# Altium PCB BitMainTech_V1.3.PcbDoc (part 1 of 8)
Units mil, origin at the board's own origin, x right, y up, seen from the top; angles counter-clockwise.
Board outline 9842.52 x 6082.68 mil, 4 copper layers (Top Layer, Mid-Layer 1, Mid-Layer 2, Bottom Layer); 987 components, 282 nets, 3694 pads, 3174 vias.
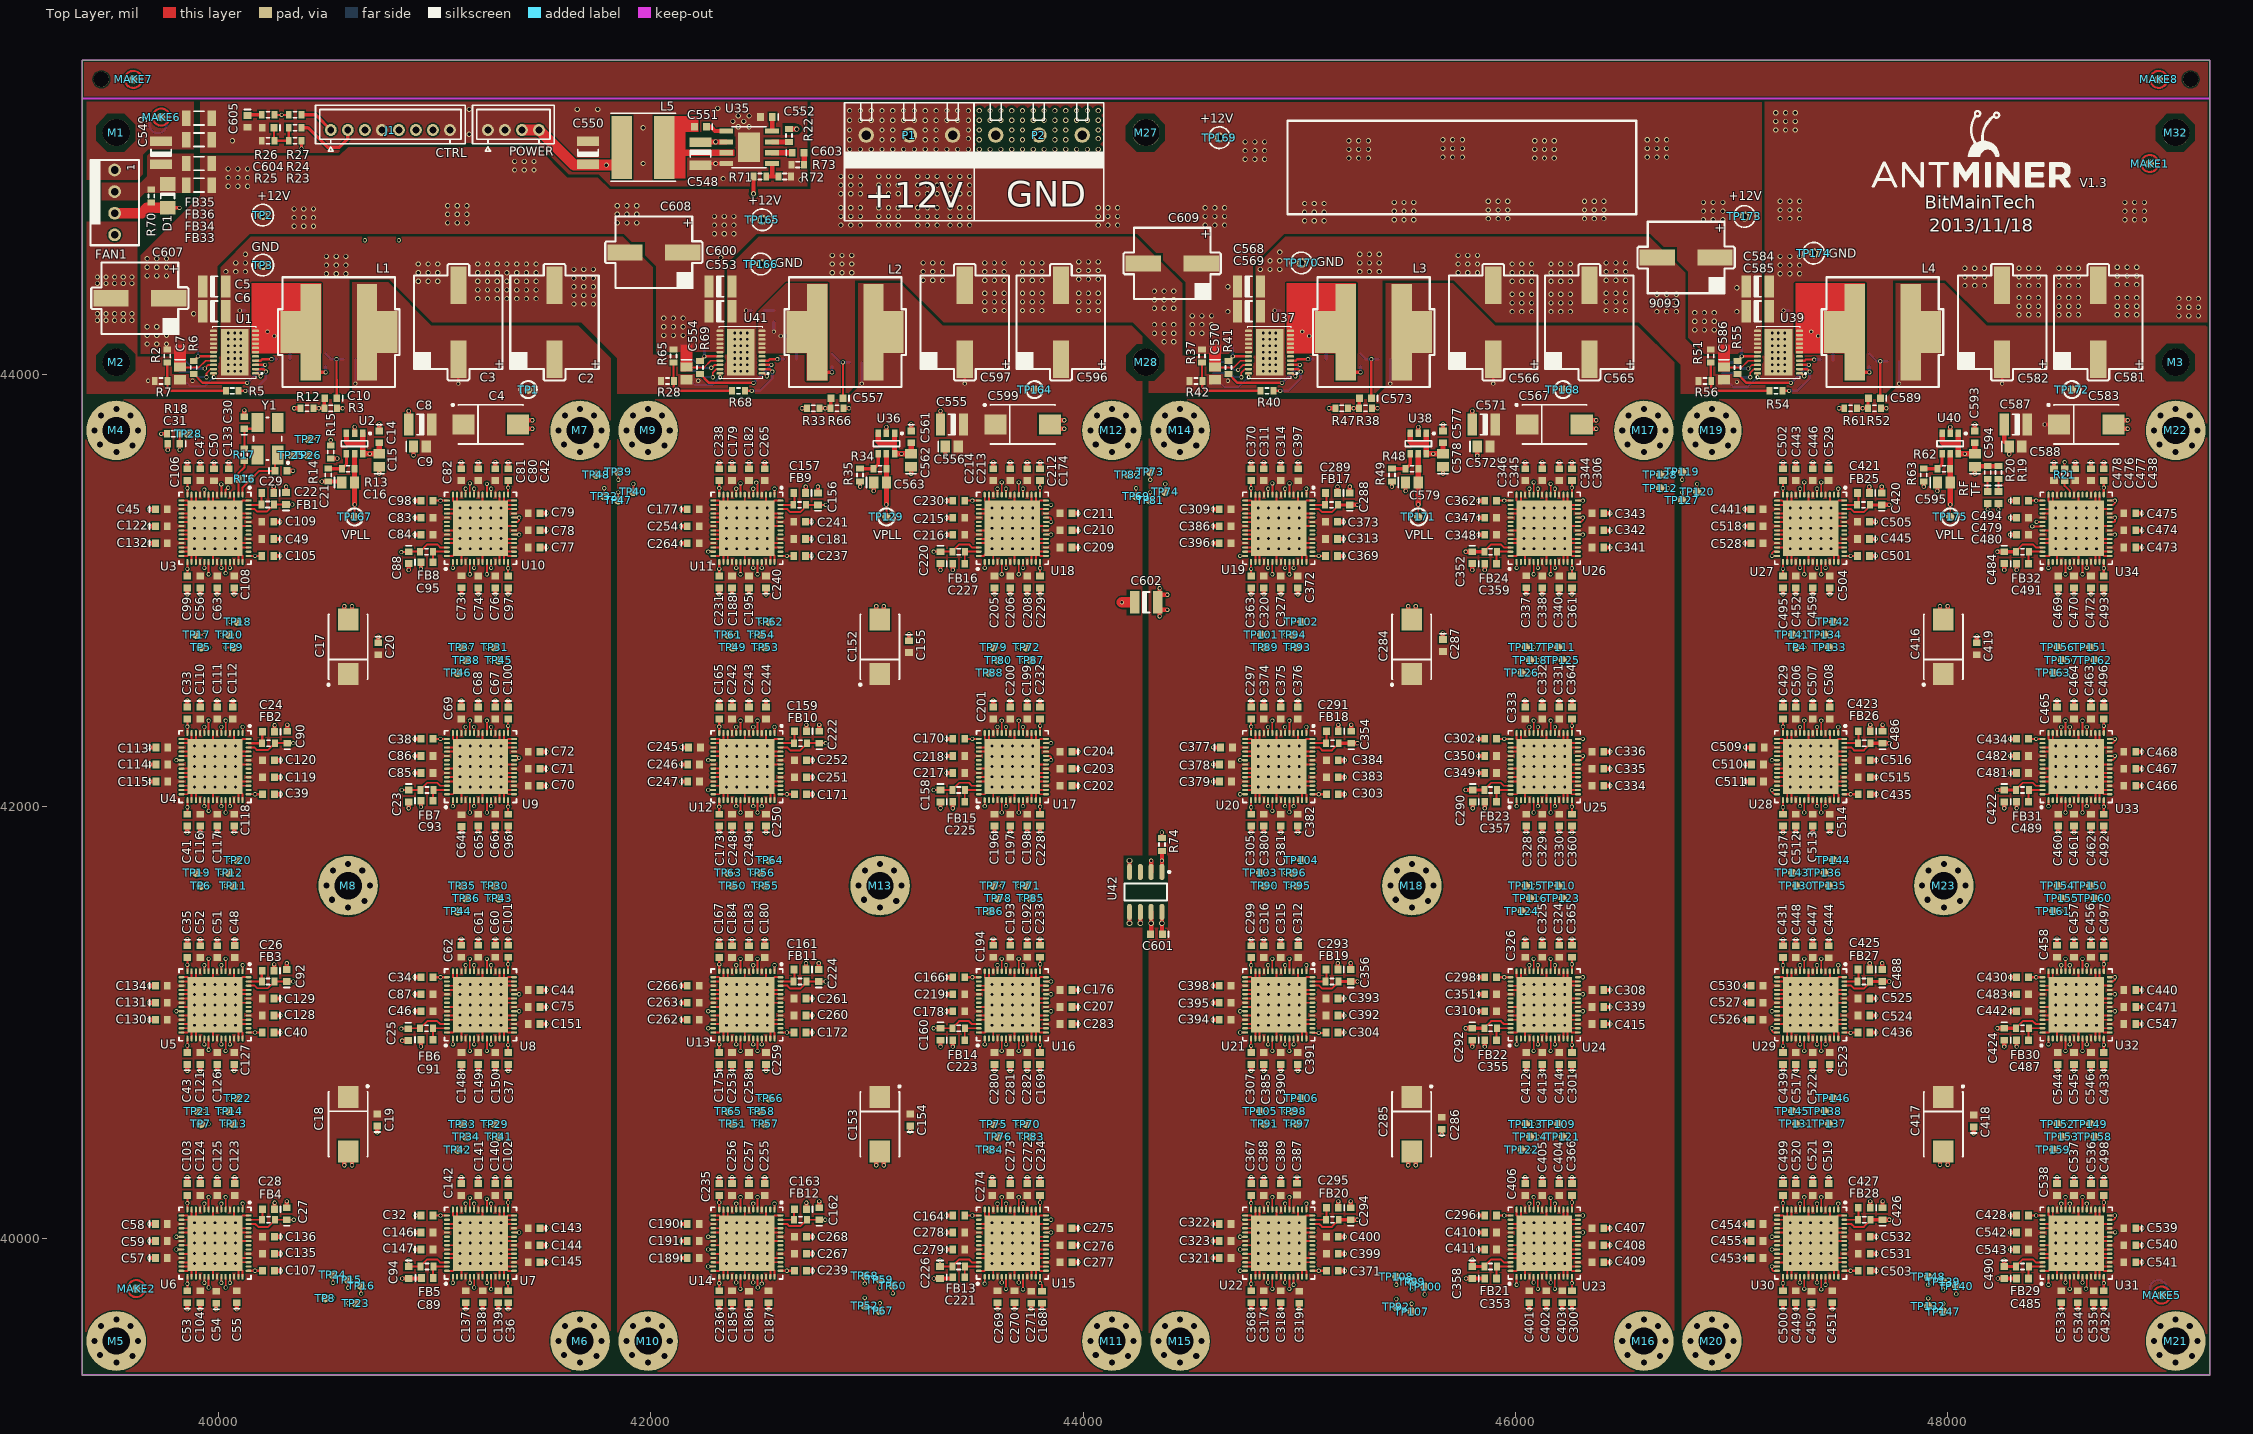
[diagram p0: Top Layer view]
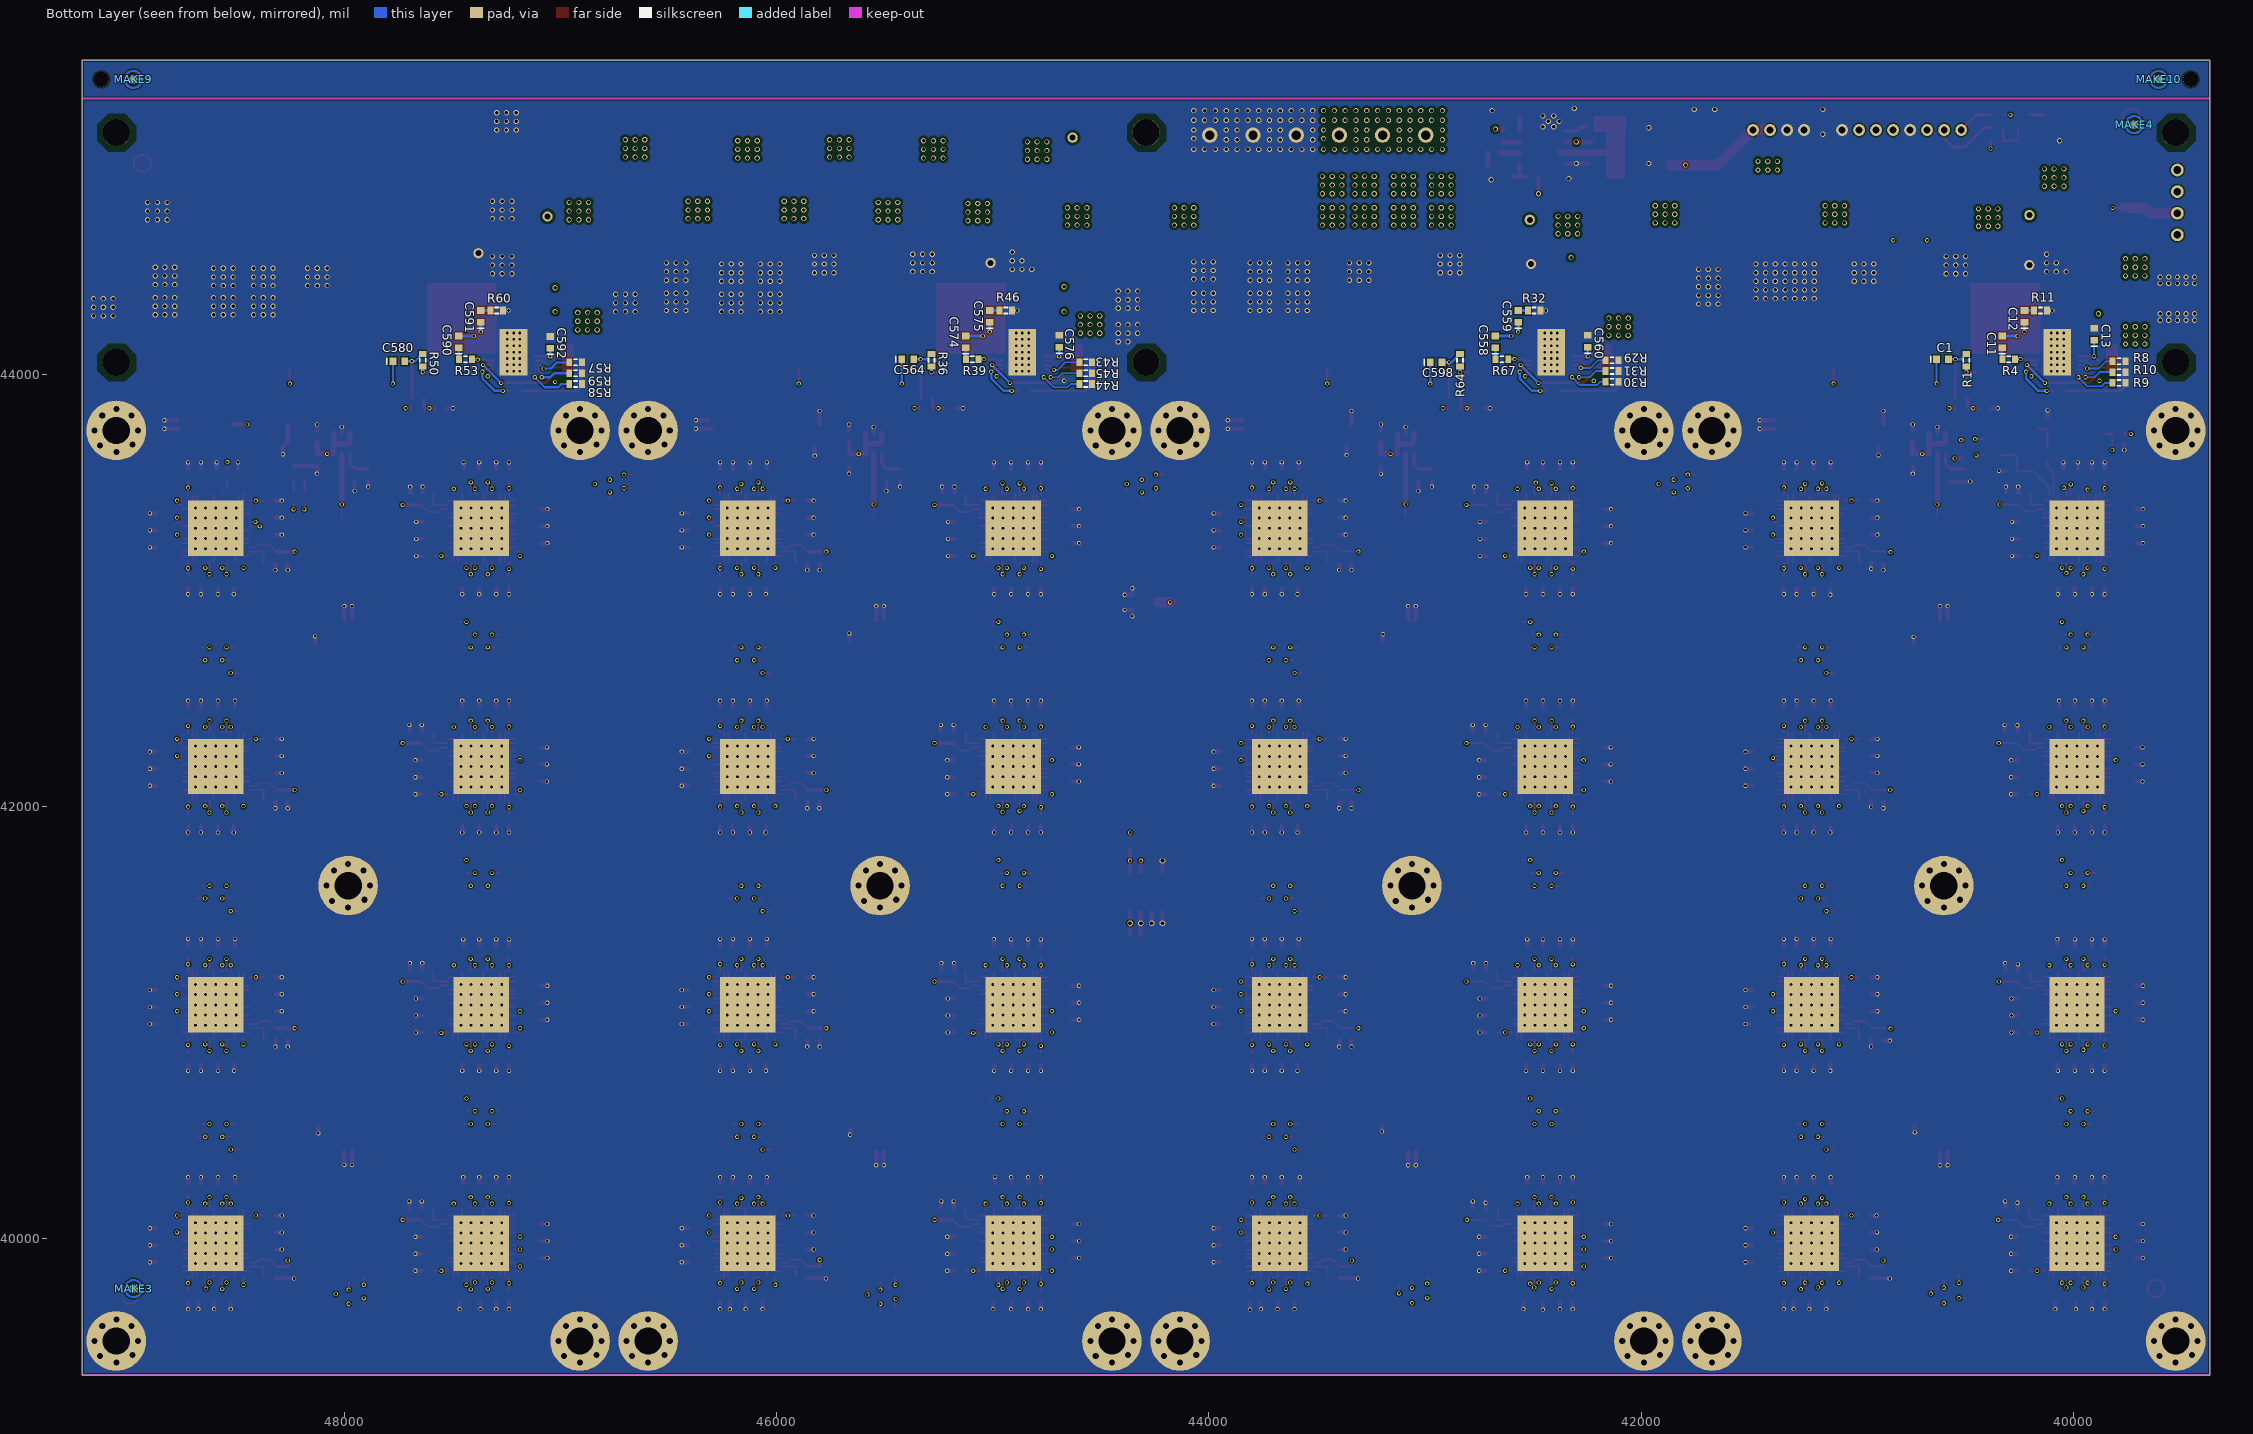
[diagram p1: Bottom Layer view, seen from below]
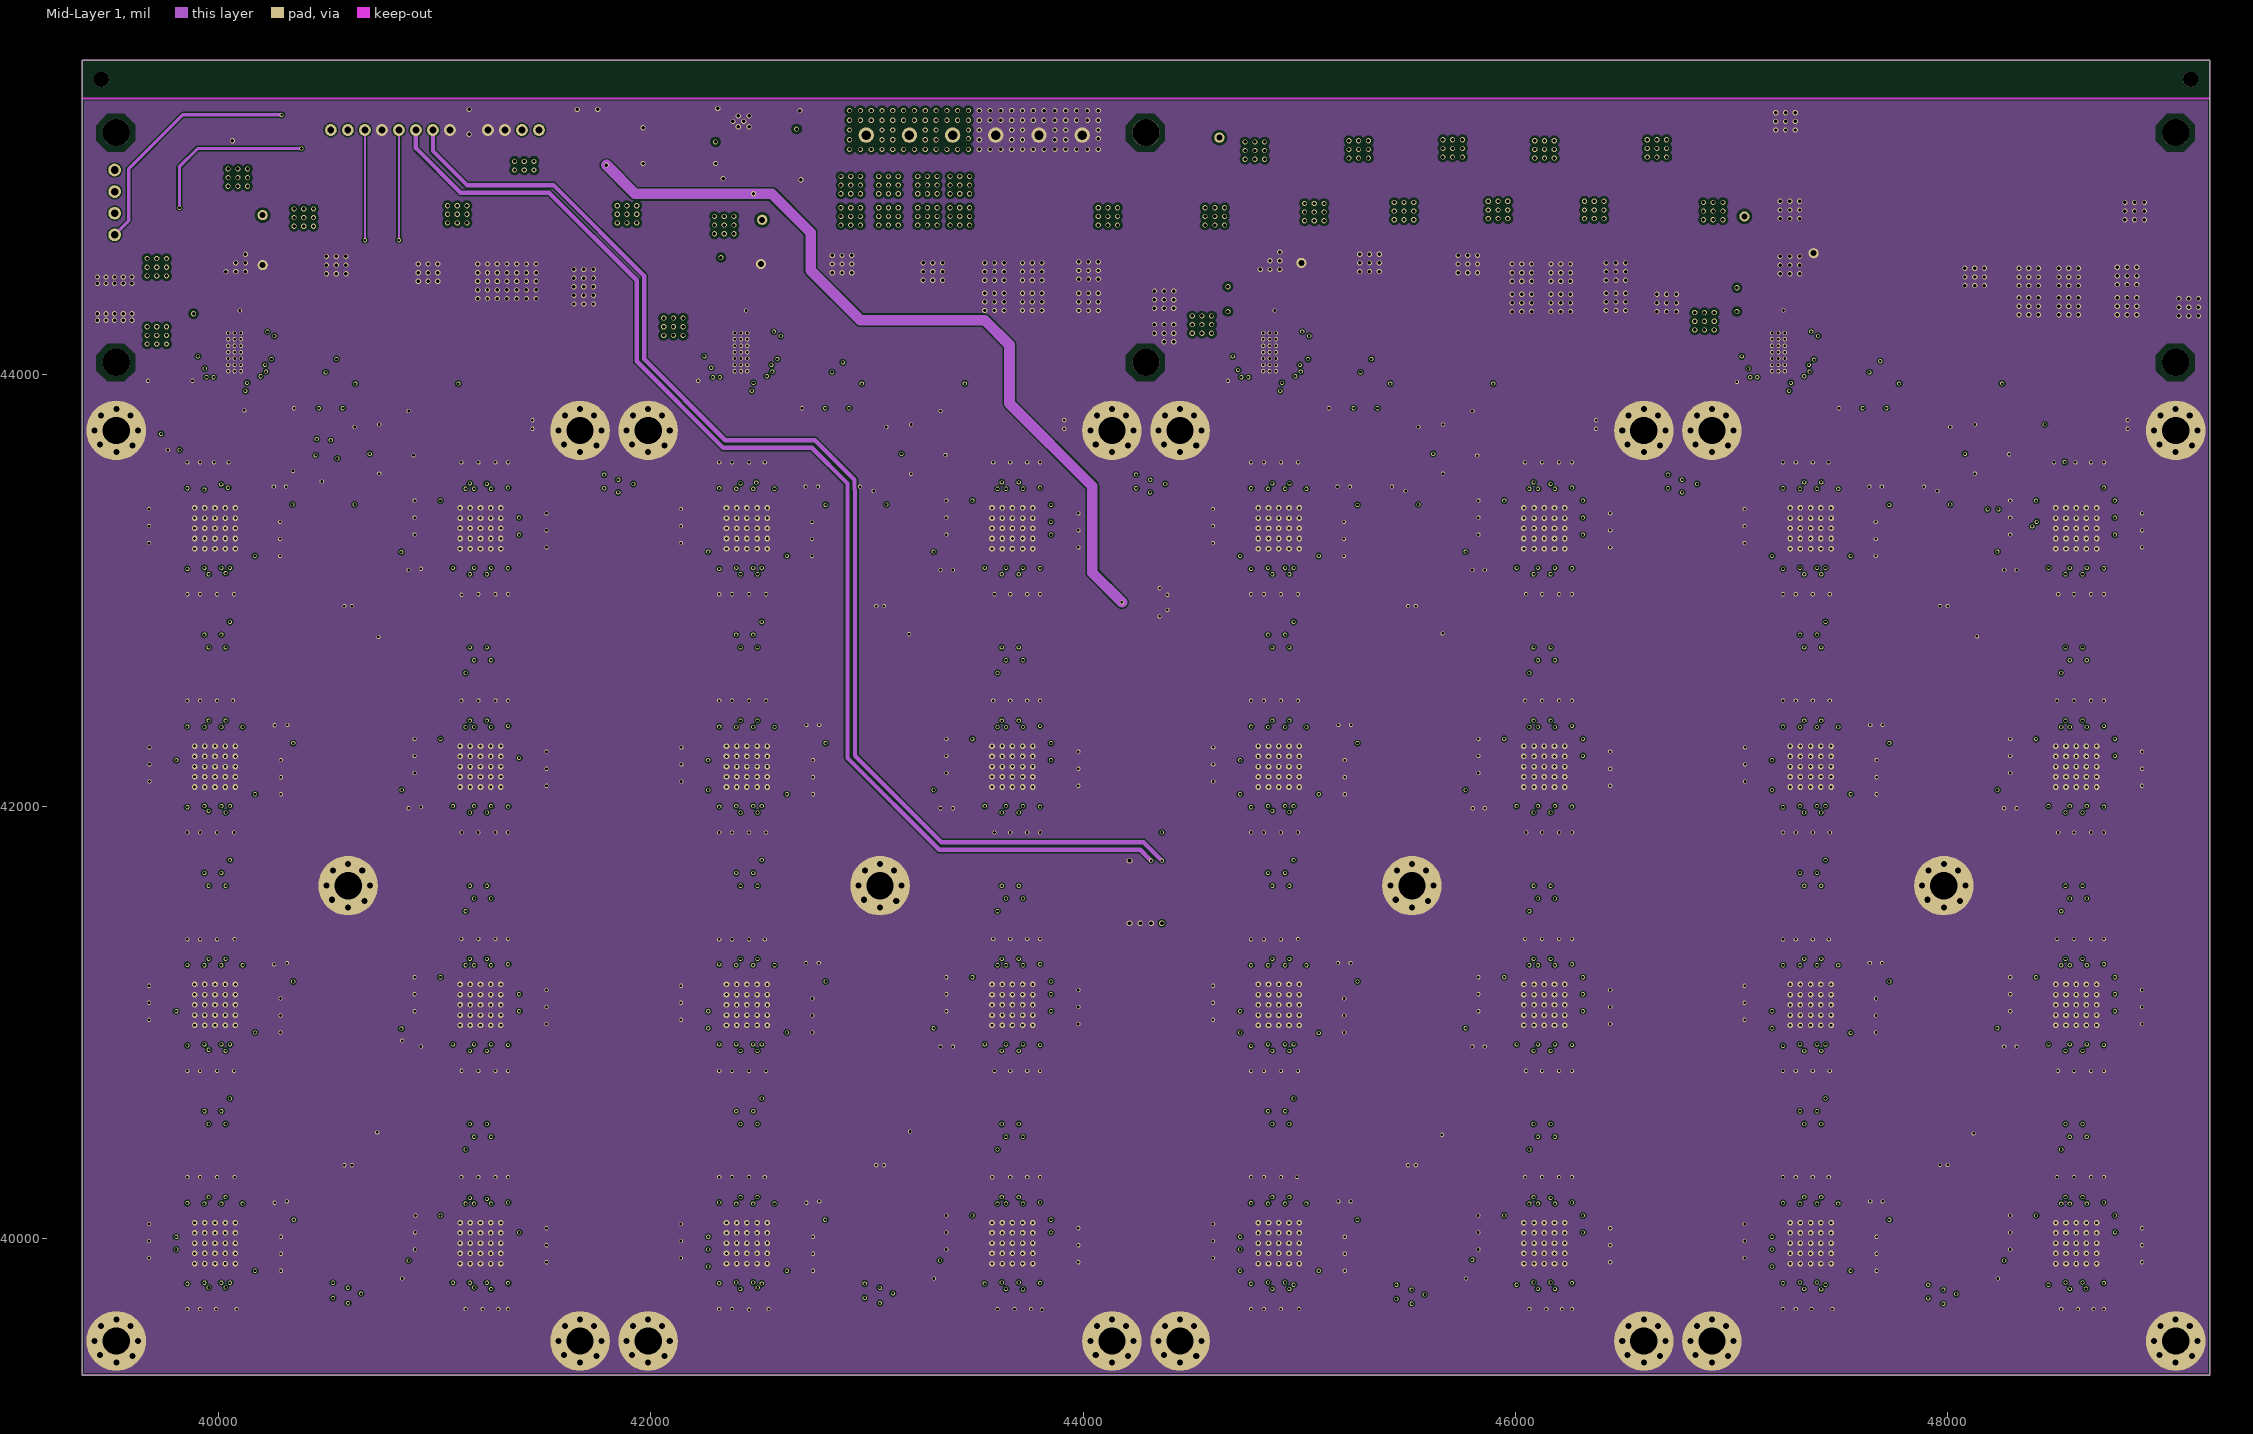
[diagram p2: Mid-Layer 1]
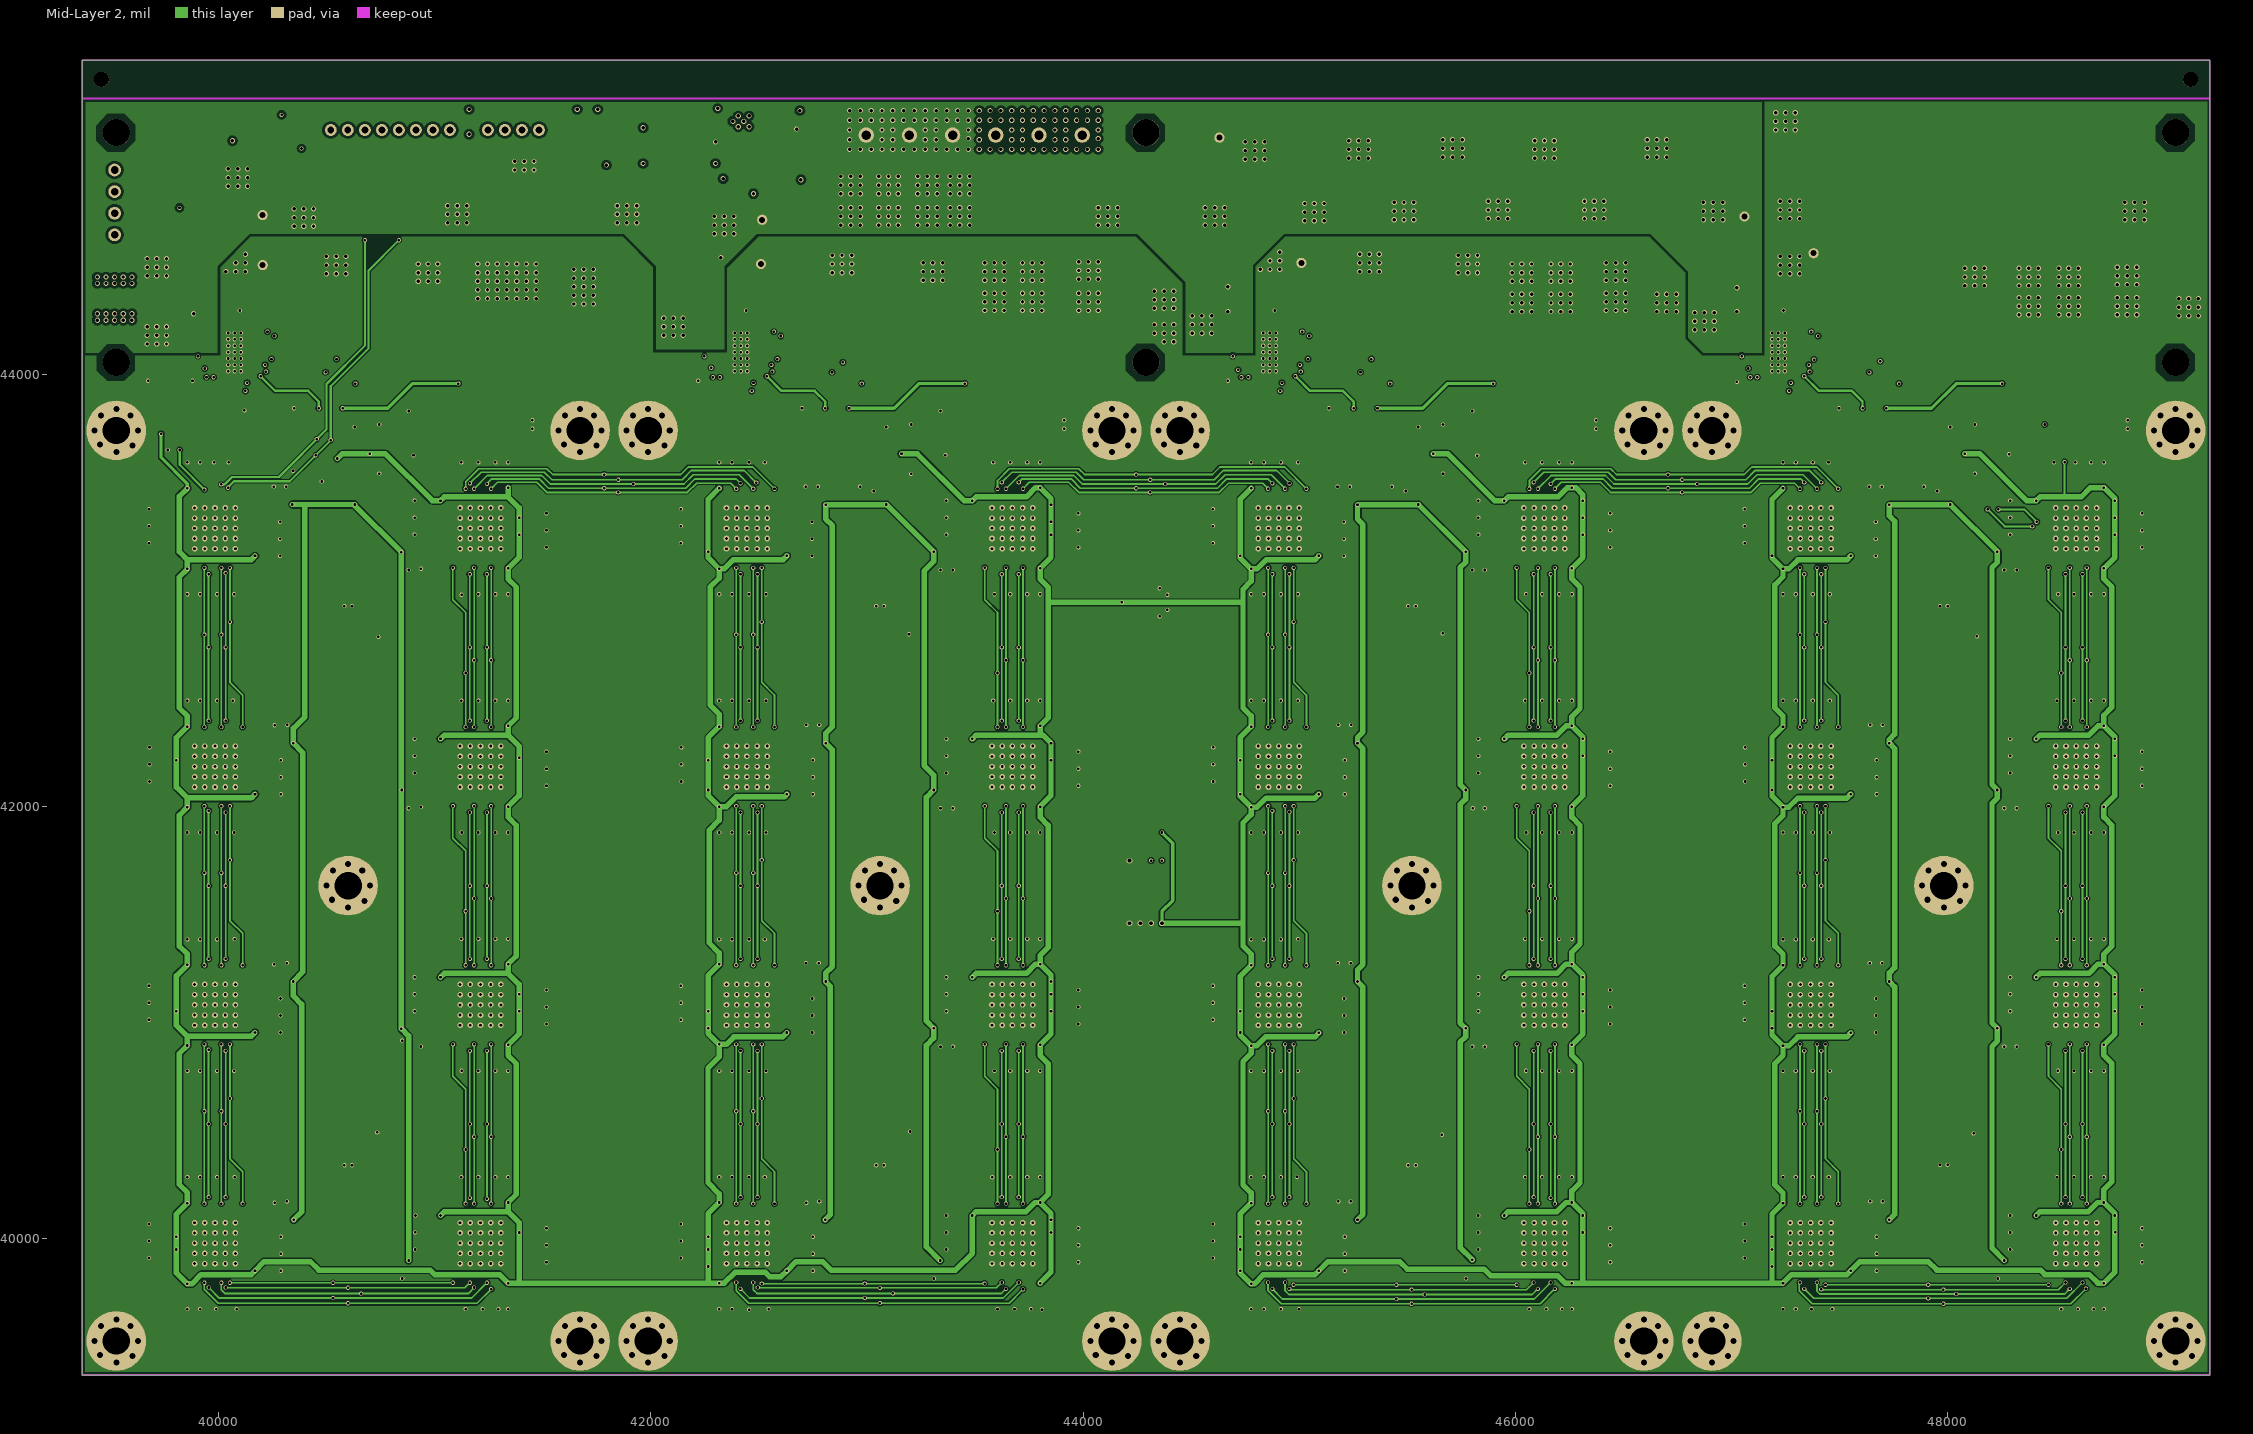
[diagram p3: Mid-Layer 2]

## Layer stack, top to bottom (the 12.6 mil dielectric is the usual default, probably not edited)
Top Layer: signal copper 1.4
Dielectric: core 12.6, FR-4, Dk 4.8
Mid-Layer 1: signal copper 1.4
Dielectric: prepreg 12.6, FR-4, Dk 4.8
Mid-Layer 2: signal copper 1.4
Dielectric: core 12.6, FR-4, Dk 4.8
Bottom Layer: signal copper 1.4

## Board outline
39370.08,45452.76 49212.6,45452.76 49212.6,39370.08 39370.08,39370.08

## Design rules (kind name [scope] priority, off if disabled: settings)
Clearance Clearance_+12V [InNet('+12V')] p1: gap=12
Clearance [All] p2: gap=6
HoleSize [All] p1: absolutevalues=TRUE maxlimit=200 minlimit=11 maxpercent=80.000 minpercent=20.000
MinimumSolderMaskSliver [All] p1: minsoldermaskwidth=0
PolygonConnect [All] p1: connectstyle=Direct reliefconductorwidth=10 reliefentries=4 polygonreliefangle="90 Angle" airgapwidth=10
RoutingVias [All] p1: holewidth=12 width=20 viastyle="Through Hole" minholewidth=12 minwidth=20 maxholewidth=200 maxwidth=200
SilkToSilkClearance [All] p1: silktosilkclearance=2
SilkToSolderMaskClearance SilkscreenOverComponentPads [IsPad] p1: minsilkscreentomaskgap=0 clearancetoexposedcopper=TRUE
SolderMaskExpansion [All] p1: expansion=4
Width Width_+12V [InNet('+12V')] p1: maxlimit=100 minlimit=15 preferedwidth=15
Width Width_VDD [InNet('VDD')] p2: maxlimit=100 minlimit=10 preferedwidth=10
Width Width_GND [InNet('GND')] p3: maxlimit=100 minlimit=8 preferedwidth=15
Width Width_PLL [InNet('VPLL')] p4: maxlimit=50 minlimit=10 preferedwidth=10
Width Width_VCC [InNet('VCC')] p5: maxlimit=50 minlimit=10 preferedwidth=10
Width [All] p6: maxlimit=100 minlimit=8 preferedwidth=8
24 further rules are at their usual default settings.

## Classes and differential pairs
component class HashUnit4: C416 C417 C418 C419 C420 C421 C422 C423 C424 C425 C426 C427 C428 C429 C430 C431 C432 C433 C434 C435 C436 C437 C438 C439 C440 C441 C442 C443 C444 C445 C446 C447 C448 C449 C450 C451 C452 C453 C454 C455 C456 C457 C458 C459 C460 C461 C462 C463 C464 C465 C466 C467 C468 C469 C470 C471 C472 C473 C474 C475 C476 C477 C478 C479 C480 C481 C482 C483 C484 C485 C486 C487 C488 C489 C490 C491 C492 C493 C494 C495 C496 C497 C498 C499 C500 C501 C502 C503 C504 C505 C506 C507 C508 C509 C510 C511 C512 C513 C514 C515 C516 C517 C518 C519 C520 C521 C522 C523 C524 C525 C526 C527 C528 C529 C530 C531 C532 C533 C534 C535 C536 C537 C538 C539 C540 C541 C542 C543 C544 C545 C546 C547 FB25 FB26 FB27 FB28 FB29 FB30 FB31 FB32 M19 M20 M21 M22 M23 R19 R20 R21 RF TF TP4 TP130 TP131 TP132 TP133 TP134 TP135 TP136 TP137 TP138 TP139 TP140 TP141 TP142 TP143 TP144 TP145 TP146 TP147 TP148 TP149 TP150 TP151 TP152 TP153 TP154 TP155 TP156 TP157 TP158 TP159 TP160 TP161 TP162 TP163 U27 U28 U29 U30 U31 U32 U33 U34
component class HashUnit3: C284 C285 C286 C287 C288 C289 C290 C291 C292 C293 C294 C295 C296 C297 C298 C299 C300 C301 C302 C303 C304 C305 C306 C307 C308 C309 C310 C311 C312 C313 C314 C315 C316 C317 C318 C319 C320 C321 C322 C323 C324 C325 C326 C327 C328 C329 C330 C331 C332 C333 C334 C335 C336 C337 C338 C339 C340 C341 C342 C343 C344 C345 C346 C347 C348 C349 C350 C351 C352 C353 C354 C355 C356 C357 C358 C359 C360 C361 C362 C363 C364 C365 C366 C367 C368 C369 C370 C371 C372 C373 C374 C375 C376 C377 C378 C379 C380 C381 C382 C383 C384 C385 C386 C387 C388 C389 C390 C391 C392 C393 C394 C395 C396 C397 C398 C399 C400 C401 C402 C403 C404 C405 C406 C407 C408 C409 C410 C411 C412 C413 C414 C415 FB17 FB18 FB19 FB20 FB21 FB22 FB23 FB24 M14 M15 M16 M17 M18 TP89 TP90 TP91 TP92 TP93 TP94 TP95 TP96 TP97 TP98 TP99 TP100 TP101 TP102 TP103 TP104 TP105 TP106 TP107 TP108 TP109 TP110 TP111 TP112 TP113 TP114 TP115 TP116 TP117 TP118 TP119 TP120 TP121 TP122 TP123 TP124 TP125 TP126 TP127 TP128 U19 U20 U21 U22 U23 U24 U25 U26
component class HashUnit2: C152 C153 C154 C155 C156 C157 C158 C159 C160 C161 C162 C163 C164 C165 C166 C167 C168 C169 C170 C171 C172 C173 C174 C175 C176 C177 C178 C179 C180 C181 C182 C183 C184 C185 C186 C187 C188 C189 C190 C191 C192 C193 C194 C195 C196 C197 C198 C199 C200 C201 C202 C203 C204 C205 C206 C207 C208 C209 C210 C211 C212 C213 C214 C215 C216 C217 C218 C219 C220 C221 C222 C223 C224 C225 C226 C227 C228 C229 C230 C231 C232 C233 C234 C235 C236 C237 C238 C239 C240 C241 C242 C243 C244 C245 C246 C247 C248 C249 C250 C251 C252 C253 C254 C255 C256 C257 C258 C259 C260 C261 C262 C263 C264 C265 C266 C267 C268 C269 C270 C271 C272 C273 C274 C275 C276 C277 C278 C279 C280 C281 C282 C283 FB9 FB10 FB11 FB12 FB13 FB14 FB15 FB16 M9 M10 M11 M12 M13 TP49 TP50 TP51 TP52 TP53 TP54 TP55 TP56 TP57 TP58 TP59 TP60 TP61 TP62 TP63 TP64 TP65 TP66 TP67 TP68 TP69 TP70 TP71 TP72 TP73 TP74 TP75 TP76 TP77 TP78 TP79 TP80 TP81 TP82 TP83 TP84 TP85 TP86 TP87 TP88 U11 U12 U13 U14 U15 U16 U17 U18
component class HashUnit1: C17 C18 C19 C20 C21 C22 C23 C24 C25 C26 C27 C28 C29 C30 C31 C32 C33 C34 C35 C36 C37 C38 C39 C40 C41 C42 C43 C44 C45 C46 C47 C48 C49 C50 C51 C52 C53 C54 C55 C56 C57 C58 C59 C60 C61 C62 C63 C64 C65 C66 C67 C68 C69 C70 C71 C72 C73 C74 C75 C76 C77 C78 C79 C80 C81 C82 C83 C84 C85 C86 C87 C88 C89 C90 C91 C92 C93 C94 C95 C96 C97 C98 C99 C100 C101 C102 C103 C104 C105 C106 C107 C108 C109 C110 C111 C112 C113 C114 C115 C116 C117 C118 C119 C120 C121 C122 C123 C124 C125 C126 C127 C128 C129 C130 C131 C132 C133 C134 C135 C136 C137 C138 C139 C140 C141 C142 C143 C144 C145 C146 C147 C148 C149 C150 C151 FB1 FB2 FB3 FB4 FB5 FB6 FB7 FB8 M4 M5 M6 M7 M8 R15 R16 R17 R18 TP5 TP6 TP7 TP8 TP9 TP10 TP11 TP12 TP13 TP14 TP15 TP16 TP17 TP18 TP19 TP20 TP21 TP22 TP23 TP24 TP25 TP26 TP27 TP28 TP29 TP30 TP31 TP32 TP33 TP34 TP35 TP36 TP37 TP38 TP39 TP40 TP41 TP42 TP43 TP44 TP45 TP46 TP47 TP48 U3 U4 U5 U6 U7 U8 U9 U10 Y1
component class HashPower1: C1 C2 C3 C4 C5 C6 C7 C8 C9 C10 C11 C12 C13 C14 C15 C16 C606 L1 M1 M2 R1 R2 R3 R4 R5 R6 R7 R8 R9 R10 R11 R12 R13 R14 TP1 TP2 TP3 TP167 U1 U2
component class TOP: C548 C549 C550 C551 C552 C601 C602 C603 C604 C605 D1 FAN1 FB33 FB34 FB35 FB36 J1 L5 MAKE1 MAKE2 MAKE3 MAKE4 MAKE5 MAKE6 MAKE7 MAKE8 MAKE9 MAKE10 P1 P2 POWER R22 R23 R24 R25 R26 R27 R70 R71 R72 R73 R74 U35 U42
component class HashPower2: C553 C554 C555 C556 C557 C558 C559 C560 C561 C562 C563 C596 C597 C598 C599 C600 C607 L2 R28 R29 R30 R31 R32 R33 R34 R35 R64 R65 R66 R67 R68 R69 TP129 TP164 TP165 TP166 U36 U41
component class HashPower3: C564 C565 C566 C567 C568 C569 C570 C571 C572 C573 C574 C575 C576 C577 C578 C579 C608 L3 M27 M28 R36 R37 R38 R39 R40 R41 R42 R43 R44 R45 R46 R47 R48 R49 TP168 TP169 TP170 TP171 U37 U38
component class HashPower4: C580 C581 C582 C583 C584 C585 C586 C587 C588 C589 C590 C591 C592 C593 C594 C595 C609 L4 M3 M32 R50 R51 R52 R53 R54 R55 R56 R57 R58 R59 R60 R61 R62 R63 TP172 TP173 TP174 TP175 U39 U40

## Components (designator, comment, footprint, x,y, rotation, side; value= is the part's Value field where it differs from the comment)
C1 "22nF" CC0603(1608) 40606.3,44070 r180 bottom
C2 "1500uF/4V" F12 41555.12,44240.16 r0 top locked
C3 "1500uF/4V" F12 41110.24,44240.16 r0 top locked
C4 "680uF/6.3V" D 41259.84,43767.72 r0 top
C5 "22uF" CC1210(3225) 39980.32,44405.51 r180 top
C6 "22uF" CC1210(3225) 39980.32,44291.34 r180 top
C7 "4.7uF" CC0805(2012) 39822.83,44003.94 r270 top
C8 "47uF" CAPC3225L 40933.07,43767.72 r180 top
C9 "10uF" CAPC2012L 40932,43666 r0 top
C10 "1nF" CC0603(1608) 40519.68,43889.76 r180 top
C11 "100nF" CC0603(1608) 40330,44150 r90 bottom
C12 "2200pF" CC0603(1608) 40227,44268 r90 bottom
C13 "1uF" CC0603(1608) 39905,44185 r90 bottom
C14 "100nF" CC0603(1608) 40744.09,43710.63 r270 top
C15 "10uF" CC0805(2012) 40744.09,43602.36 r90 top
C16 "10uF" CC0805(2012) 40600.39,43500 r0 top
C17 "680uF/6.3V" D 40600,42739.02 r90 top
C18 "680uF/6.3V" D 40600,40530.98 r270 top
C19 "100nF" CC0603(1608) 40735,40550 r90 top
C20 "100nF" CC0603(1608) 40740,42730 r270 top
C21 "100nF" CC0603(1608) 40312.99,43425.2 r90 top
C22 "100nF" CC0603(1608) 40228.35,43450.79 r180 top
C23 "100nF" CC0603(1608) 40879.92,42049.21 r270 top
C24 "100nF" CC0603(1608) 40232.28,42346.46 r180 top
C25 "100nF" CC0603(1608) 40877.95,40944.88 r270 top
C26 "100nF" CC0603(1608) 40230.32,41240.16 r180 top
C27 "100nF" CC0603(1608) 40316.93,40116.14 r90 top
C28 "100nF" CC0603(1608) 40232.28,40137.8 r180 top
C29 "8pF" CC0603(1608) 40289.37,43553.15 r0 top
C30 "8pF" CC0603(1608) 40120.08,43775.59 r90 top
C31 "10uF" CC0603(1608) 39793.31,43679.13 r180 top
C32 "100nF" CC0603(1608) 40964.57,40108.27 r0 top
C33 "100nF" CC0603(1608) 39856.3,42433.07 r270 top
C34 "100nF" CC0603(1608) 40964.57,41210.63 r0 top
C35 "100nF" CC0603(1608) 39856.3,41328.74 r270 top
C36 "100nF" CC0603(1608) 41340.55,39732.28 r90 top
C37 "100nF" CC0603(1608) 41340.55,40834.65 r90 top
C38 "100nF" CC0603(1608) 40964.57,42312.99 r0 top
C39 "100nF" CC0603(1608) 40232.28,42057.09 r180 top
C40 "100nF" CC0603(1608) 40230.32,40954.72 r180 top
C41 "100nF" CC0603(1608) 39856.3,41937.01 r90 top
C42 "100nF" CC0603(1608) 41340.55,43535.43 r270 top
C43 "100nF" CC0603(1608) 39856.3,40834.65 r90 top
C44 "100nF" CC0603(1608) 41460.63,41151.57 r180 top
C45 "100nF" CC0603(1608) 39736.22,43375.98 r0 top
C46 "100nF" CC0603(1608) 40964.57,41053.15 r0 top
C47 "100nF" CC0603(1608) 39915.35,43535.43 r270 top
C48 "100nF" CC0603(1608) 40075,41330 r270 top
C49 "100nF" CC0603(1608) 40228.35,43238.19 r180 top
C50 "100nF" CC0603(1608) 39980,43535 r270 top
C51 "100nF" CC0603(1608) 39994.09,41328.74 r270 top
C52 "100nF" CC0603(1608) 39915.35,41328.74 r270 top
C53 "100nF" CC0603(1608) 39915.35,39732.28 r90 top
C54 "100nF" CC0603(1608) 39990,39730 r90 top
C55 "100nF" CC0603(1608) 40084.65,39732.28 r90 top
C56 "100nF" CC0603(1608) 39915.35,43039.37 r90 top
C57 "100nF" CC0603(1608) 39736.22,39911.42 r0 top
C58 "100nF" CC0603(1608) 39736.22,40068.9 r0 top
C59 "100nF" CC0603(1608) 39736.22,39990.16 r0 top
C60 "100nF" CC0603(1608) 41281.5,41330.71 r270 top
C61 "100nF" CC0603(1608) 41202.76,41330.71 r270 top
C62 "100nF" CC0603(1608) 41124.02,41330.71 r270 top
C63 "100nF" CC0603(1608) 39994.09,43039.37 r90 top
C64 "100nF" CC0603(1608) 41125,41935 r90 top
C65 "100nF" CC0603(1608) 41202.76,41937.01 r90 top
C66 "100nF" CC0603(1608) 41281.5,41937.01 r90 top
C67 "100nF" CC0603(1608) 41281.5,42433.07 r270 top
C68 "100nF" CC0603(1608) 41202.76,42433.07 r270 top
C69 "100nF" CC0603(1608) 41124.02,42433.07 r270 top
C70 "100nF" CC0603(1608) 41460.63,42096.46 r180 top
C71 "100nF" CC0603(1608) 41460.63,42175.2 r180 top
C72 "100nF" CC0603(1608) 41460.63,42253.94 r180 top
C73 "100nF" CC0603(1608) 41125,43040 r90 top
C74 "100nF" CC0603(1608) 41202.76,43039.37 r90 top
C75 "100nF" CC0603(1608) 41460.63,41072.83 r180 top
C76 "100nF" CC0603(1608) 41281.5,43039.37 r90 top
C77 "100nF" CC0603(1608) 41460.63,43198.82 r180 top
C78 "100nF" CC0603(1608) 41460.63,43277.56 r180 top
C79 "100nF" CC0603(1608) 41460.63,43356.3 r180 top
C80 "100nF" CC0603(1608) 41281.5,43535.43 r270 top
C81 "100nF" CC0603(1608) 41202.76,43535.43 r270 top
C82 "100nF" CC0603(1608) 41124.02,43535.43 r270 top
C83 "100nF" CC0603(1608) 40964.57,43336.61 r0 top
C84 "100nF" CC0603(1608) 40964.57,43257.87 r0 top
C85 "100nF" CC0603(1608) 40964.57,42155.51 r0 top
C86 "100nF" CC0603(1608) 40964.57,42234.25 r0 top
C87 "100nF" CC0603(1608) 40964.57,41131.89 r0 top
C88 "100nF" CC0603(1608) 40879.92,43151.57 r270 top
C89 "100nF" CC0603(1608) 40966.54,39818.9 r0 top
C90 "100nF" CC0603(1608) 40318.9,42320.87 r90 top
C91 "100nF" CC0603(1608) 40964.57,40921.26 r0 top
C92 "100nF" CC0603(1608) 40316.93,41218.5 r90 top
C93 "100nF" CC0603(1608) 40964.57,42027.56 r0 top
C94 "100nF" CC0603(1608) 40879.92,39844.49 r270 top
C95 "100nF" CC0603(1608) 40964.57,43129.92 r0 top
C96 "100nF" CC0603(1608) 41340.55,41937.01 r90 top
C97 "100nF" CC0603(1608) 41340.55,43039.37 r90 top
C98 "100nF" CC0603(1608) 40964.57,43415.35 r0 top
C99 "100nF" CC0603(1608) 39856.3,43039.37 r90 top
C100 "100nF" CC0603(1608) 41340.55,42433.07 r270 top
C101 "100nF" CC0603(1608) 41340.55,41330.71 r270 top
C102 "100nF" CC0603(1608) 41340.55,40228.35 r270 top
C103 "100nF" CC0603(1608) 39856.3,40228.35 r270 top
C104 "100nF" CC0603(1608) 39856.3,39732.28 r90 top
C105 "100nF" CC0603(1608) 40228.35,43159.45 r180 top
C106 "100nF" CC0603(1608) 39856.3,43535.43 r270 top
C107 "100nF" CC0603(1608) 40232.28,39852.36 r180 top
C108 "100nF" CC0603(1608) 40072.83,43039.37 r90 top
C109 "100nF" CC0603(1608) 40228.35,43316.93 r180 top
C110 "100nF" CC0603(1608) 39915.35,42433.07 r270 top
C111 "100nF" CC0603(1608) 39994.09,42433.07 r270 top
C112 "100nF" CC0603(1608) 40066.93,42433.07 r270 top
C113 "100nF" CC0603(1608) 39738.19,42273.62 r0 top
C114 "100nF" CC0603(1608) 39738.19,42194.88 r0 top
C115 "100nF" CC0603(1608) 39738.19,42116.14 r0 top
C116 "100nF" CC0603(1608) 39915.35,41937.01 r90 top
C117 "100nF" CC0603(1608) 39994.09,41937.01 r90 top
C118 "100nF" CC0603(1608) 40072.83,41937.01 r90 top
C119 "100nF" CC0603(1608) 40232.28,42135.83 r180 top
C120 "100nF" CC0603(1608) 40232.28,42214.57 r180 top
C121 "100nF" CC0603(1608) 39915.35,40834.65 r90 top
C122 "100nF" CC0603(1608) 39736.22,43297.24 r0 top
C123 "100nF" CC0603(1608) 40075,40228.35 r270 top
C124 "100nF" CC0603(1608) 39915.35,40228.35 r270 top
C125 "100nF" CC0603(1608) 39994.09,40228.35 r270 top
C126 "100nF" CC0603(1608) 39994.09,40834.65 r90 top
C127 "100nF" CC0603(1608) 40072.83,40834.65 r90 top
C128 "100nF" CC0603(1608) 40230.32,41033.46 r180 top
C129 "100nF" CC0603(1608) 40230.32,41112.2 r180 top
C130 "100nF" CC0603(1608) 39736.22,41013.78 r0 top
C131 "100nF" CC0603(1608) 39736.22,41092.52 r0 top
C132 "100nF" CC0603(1608) 39736.22,43218.5 r0 top
C133 "100nF" CC0603(1608) 40047.24,43535.43 r270 top
C134 "100nF" CC0603(1608) 39736.22,41171.26 r0 top
C135 "100nF" CC0603(1608) 40232.28,39931.1 r180 top
C136 "100nF" CC0603(1608) 40232.28,40009.84 r180 top
C137 "100nF" CC0603(1608) 41143.7,39732.28 r90 top
C138 "100nF" CC0603(1608) 41222.44,39732.28 r90 top
C139 "100nF" CC0603(1608) 41295.28,39732.28 r90 top
C140 "100nF" CC0603(1608) 41281.5,40228.35 r270 top
C141 "100nF" CC0603(1608) 41202.76,40228.35 r270 top
C142 "100nF" CC0603(1608) 41124.02,40228.35 r270 top
C143 "100nF" CC0603(1608) 41460.63,40049.21 r180 top
C144 "100nF" CC0603(1608) 41460.63,39970.47 r180 top
C145 "100nF" CC0603(1608) 41460.63,39891.73 r180 top
C146 "100nF" CC0603(1608) 40964.57,40029.53 r0 top
C147 "100nF" CC0603(1608) 40964.57,39950.79 r0 top
C148 "100nF" CC0603(1608) 41125,40835 r90 top
C149 "100nF" CC0603(1608) 41202.76,40834.65 r90 top
C150 "100nF" CC0603(1608) 41281.5,40834.65 r90 top
C151 "100nF" CC0603(1608) 41460.63,40994.09 r180 top
C152 "680uF/6.3V" D 43060,42739.02 r90 top
C153 "680uF/6.3V" D 43060,40530 r270 top
C154 "100nF" CC0603(1608) 43200,40550 r90 top
C155 "100nF" CC0603(1608) 43195,42740 r270 top
C156 "100nF" CC0603(1608) 42773.62,43423.23 r90 top
C157 "100nF" CC0603(1608) 42688.98,43450.79 r180 top
C158 "100nF" CC0603(1608) 43340.55,42049.21 r270 top
C159 "100nF" CC0603(1608) 42692.91,42348.43 r180 top
C160 "100nF" CC0603(1608) 43340.55,40946.85 r270 top
C161 "100nF" CC0603(1608) 42690.94,41246.06 r180 top
C162 "100nF" CC0603(1608) 42779.53,40116.14 r90 top
C163 "100nF" CC0603(1608) 42692.91,40137.8 r180 top
C164 "100nF" CC0603(1608) 43425.2,40108.27 r0 top
C165 "100nF" CC0603(1608) 42316.93,42433.07 r270 top
C166 "100nF" CC0603(1608) 43425.2,41210.63 r0 top
C167 "100nF" CC0603(1608) 42316.93,41328.74 r270 top
C168 "100nF" CC0603(1608) 43810,39730 r90 top
C169 "100nF" CC0603(1608) 43801.18,40834.65 r90 top
C170 "100nF" CC0603(1608) 43425.2,42312.99 r0 top
C171 "100nF" CC0603(1608) 42692.91,42057.09 r180 top
C172 "100nF" CC0603(1608) 42690.94,40954.72 r180 top
C173 "100nF" CC0603(1608) 42316.93,41937.01 r90 top
C174 "100nF" CC0603(1608) 43801.18,43535.43 r270 top
C175 "100nF" CC0603(1608) 42316.93,40834.65 r90 top
C176 "100nF" CC0603(1608) 43921.26,41151.57 r180 top
C177 "100nF" CC0603(1608) 42196.85,43375.98 r0 top
C178 "100nF" CC0603(1608) 43425.2,41053.15 r0 top
C179 "100nF" CC0603(1608) 42375.98,43535.43 r270 top
C180 "100nF" CC0603(1608) 42527.56,41328.74 r270 top
C181 "100nF" CC0603(1608) 42688.98,43238.19 r180 top
C182 "100nF" CC0603(1608) 42454.72,43535.43 r270 top
C183 "100nF" CC0603(1608) 42454.72,41328.74 r270 top
C184 "100nF" CC0603(1608) 42375.98,41328.74 r270 top
C185 "100nF" CC0603(1608) 42375.98,39732.28 r90 top
C186 "100nF" CC0603(1608) 42455,39730 r90 top
C187 "100nF" CC0603(1608) 42545.28,39732.28 r90 top
C188 "100nF" CC0603(1608) 42375.98,43039.37 r90 top
C189 "100nF" CC0603(1608) 42196.85,39911.42 r0 top
C190 "100nF" CC0603(1608) 42196.85,40068.9 r0 top
C191 "100nF" CC0603(1608) 42196.85,39990.16 r0 top
C192 "100nF" CC0603(1608) 43742.13,41330.71 r270 top
C193 "100nF" CC0603(1608) 43663.39,41330.71 r270 top
C194 "100nF" CC0603(1608) 43584.65,41330.71 r270 top
C195 "100nF" CC0603(1608) 42454.72,43039.37 r90 top
C196 "100nF" CC0603(1608) 43590.55,41937.01 r90 top
C197 "100nF" CC0603(1608) 43663.39,41937.01 r90 top
C198 "100nF" CC0603(1608) 43742.13,41937.01 r90 top
C199 "100nF" CC0603(1608) 43742.13,42433.07 r270 top
C200 "100nF" CC0603(1608) 43663.39,42433.07 r270 top
C201 "100nF" CC0603(1608) 43584.65,42433.07 r270 top
C202 "100nF" CC0603(1608) 43921.26,42096.46 r180 top
C203 "100nF" CC0603(1608) 43921.26,42175.2 r180 top
C204 "100nF" CC0603(1608) 43921.26,42253.94 r180 top
C205 "100nF" CC0603(1608) 43590.55,43039.37 r90 top
C206 "100nF" CC0603(1608) 43663.39,43039.37 r90 top
C207 "100nF" CC0603(1608) 43921.26,41072.83 r180 top
C208 "100nF" CC0603(1608) 43742.13,43039.37 r90 top
C209 "100nF" CC0603(1608) 43921.26,43198.82 r180 top
C210 "100nF" CC0603(1608) 43921.26,43277.56 r180 top
C211 "100nF" CC0603(1608) 43921.26,43356.3 r180 top
C212 "100nF" CC0603(1608) 43742.13,43535.43 r270 top
C213 "100nF" CC0603(1608) 43663.39,43535.43 r270 top
C214 "100nF" CC0603(1608) 43584.65,43535.43 r270 top
C215 "100nF" CC0603(1608) 43425.2,43336.61 r0 top
C216 "100nF" CC0603(1608) 43425.2,43257.87 r0 top
C217 "100nF" CC0603(1608) 43425.2,42155.51 r0 top
C218 "100nF" CC0603(1608) 43425.2,42234.25 r0 top
C219 "100nF" CC0603(1608) 43425.2,41131.89 r0 top
C220 "100nF" CC0603(1608) 43340.55,43151.57 r270 top
C221 "100nF" CC0603(1608) 43425.2,39822.83 r0 top
C222 "100nF" CC0603(1608) 42779.53,42320.87 r90 top
C223 "100nF" CC0603(1608) 43425.2,40919.29 r0 top
C224 "100nF" CC0603(1608) 42777.56,41218.5 r90 top
C225 "100nF" CC0603(1608) 43425.2,42021.65 r0 top
C226 "100nF" CC0603(1608) 43338.58,39844.49 r270 top
C227 "100nF" CC0603(1608) 43425.2,43124.02 r0 top
C228 "100nF" CC0603(1608) 43801.18,41937.01 r90 top
C229 "100nF" CC0603(1608) 43801.18,43039.37 r90 top
C230 "100nF" CC0603(1608) 43425.2,43415.35 r0 top
C231 "100nF" CC0603(1608) 42316.93,43039.37 r90 top
C232 "100nF" CC0603(1608) 43801.18,42433.07 r270 top
C233 "100nF" CC0603(1608) 43801.18,41330.71 r270 top
C234 "100nF" CC0603(1608) 43801.18,40228.35 r270 top
C235 "100nF" CC0603(1608) 42316.93,40228.35 r270 top
C236 "100nF" CC0603(1608) 42316.93,39732.28 r90 top
C237 "100nF" CC0603(1608) 42688.98,43159.45 r180 top
C238 "100nF" CC0603(1608) 42316.93,43535.43 r270 top
C239 "100nF" CC0603(1608) 42692.91,39852.36 r180 top
C240 "100nF" CC0603(1608) 42533.46,43039.37 r90 top
C241 "100nF" CC0603(1608) 42688.98,43316.93 r180 top
C242 "100nF" CC0603(1608) 42375.98,42433.07 r270 top
C243 "100nF" CC0603(1608) 42454.72,42433.07 r270 top
C244 "100nF" CC0603(1608) 42533.46,42433.07 r270 top
C245 "100nF" CC0603(1608) 42202.76,42273.62 r0 top
C246 "100nF" CC0603(1608) 42198.82,42194.88 r0 top
C247 "100nF" CC0603(1608) 42198.82,42116.14 r0 top
C248 "100nF" CC0603(1608) 42375.98,41937.01 r90 top
C249 "100nF" CC0603(1608) 42454.72,41937.01 r90 top
C250 "100nF" CC0603(1608) 42533.46,41937.01 r90 top
C251 "100nF" CC0603(1608) 42692.91,42135.83 r180 top
C252 "100nF" CC0603(1608) 42692.91,42214.57 r180 top
C253 "100nF" CC0603(1608) 42375.98,40834.65 r90 top
C254 "100nF" CC0603(1608) 42196.85,43297.24 r0 top
C255 "100nF" CC0603(1608) 42527.56,40228.35 r270 top
C256 "100nF" CC0603(1608) 42375.98,40228.35 r270 top
C257 "100nF" CC0603(1608) 42454.72,40228.35 r270 top
C258 "100nF" CC0603(1608) 42454.72,40834.65 r90 top
C259 "100nF" CC0603(1608) 42533.46,40834.65 r90 top
C260 "100nF" CC0603(1608) 42690.94,41033.46 r180 top
C261 "100nF" CC0603(1608) 42690.94,41112.2 r180 top
C262 "100nF" CC0603(1608) 42196.85,41013.78 r0 top
C263 "100nF" CC0603(1608) 42196.85,41092.52 r0 top
C264 "100nF" CC0603(1608) 42196.85,43218.5 r0 top
C265 "100nF" CC0603(1608) 42527.56,43535.43 r270 top
C266 "100nF" CC0603(1608) 42196.85,41171.26 r0 top
C267 "100nF" CC0603(1608) 42692.91,39931.1 r180 top
C268 "100nF" CC0603(1608) 42692.91,40009.84 r180 top
C269 "100nF" CC0603(1608) 43604.33,39732.28 r90 top
C270 "100nF" CC0603(1608) 43683.07,39732.28 r90 top
C271 "100nF" CC0603(1608) 43760,39730 r90 top
C272 "100nF" CC0603(1608) 43742.13,40228.35 r270 top
C273 "100nF" CC0603(1608) 43663.39,40228.35 r270 top
C274 "100nF" CC0603(1608) 43580,40228.35 r270 top
C275 "100nF" CC0603(1608) 43921.26,40049.21 r180 top
C276 "100nF" CC0603(1608) 43921.26,39970.47 r180 top
C277 "100nF" CC0603(1608) 43921.26,39891.73 r180 top
C278 "100nF" CC0603(1608) 43425.2,40029.53 r0 top
C279 "100nF" CC0603(1608) 43425.2,39950.79 r0 top
C280 "100nF" CC0603(1608) 43590.55,40834.65 r90 top
C281 "100nF" CC0603(1608) 43663.39,40834.65 r90 top
C282 "100nF" CC0603(1608) 43742.13,40834.65 r90 top
C283 "100nF" CC0603(1608) 43921.26,40994.09 r180 top
C284 "680uF/6.3V" D 45520,42739.02 r90 top
C285 "680uF/6.3V" D 45520,40530 r270 top
C286 "100nF" CC0603(1608) 45660,40535 r90 top
C287 "100nF" CC0603(1608) 45665,42745 r270 top
C288 "100nF" CC0603(1608) 45234.23,43423.23 r90 top
C289 "100nF" CC0603(1608) 45149.59,43450.79 r180 top
C290 "100nF" CC0603(1608) 45803.13,42049.21 r270 top
C291 "100nF" CC0603(1608) 45153.53,42348.43 r180 top
C292 "100nF" CC0603(1608) 45801.16,40946.85 r270 top
C293 "100nF" CC0603(1608) 45151.56,41246.06 r180 top
C294 "100nF" CC0603(1608) 45238.17,40116.14 r90 top
C295 "100nF" CC0603(1608) 45153.53,40143.7 r180 top
C296 "100nF" CC0603(1608) 45885.83,40108.27 r0 top
C297 "100nF" CC0603(1608) 44777.56,42433.07 r270 top
C298 "100nF" CC0603(1608) 45885.83,41210.63 r0 top
C299 "100nF" CC0603(1608) 44777.56,41328.74 r270 top
C300 "100nF" CC0603(1608) 46261.81,39732.28 r90 top
C301 "100nF" CC0603(1608) 46261.81,40834.65 r90 top
C302 "100nF" CC0603(1608) 45885.83,42312.99 r0 top
C303 "100nF" CC0603(1608) 45153.54,42057.09 r180 top
C304 "100nF" CC0603(1608) 45151.57,40954.72 r180 top
C305 "100nF" CC0603(1608) 44777.56,41937.01 r90 top
C306 "100nF" CC0603(1608) 46261.81,43535.43 r270 top
C307 "100nF" CC0603(1608) 44777.56,40834.65 r90 top
C308 "100nF" CC0603(1608) 46381.89,41151.57 r180 top
C309 "100nF" CC0603(1608) 44657.48,43375.98 r0 top
C310 "100nF" CC0603(1608) 45885.83,41053.15 r0 top
C311 "100nF" CC0603(1608) 44836.61,43535.43 r270 top
C312 "100nF" CC0603(1608) 44995,41330 r270 top
C313 "100nF" CC0603(1608) 45149.61,43238.19 r180 top
C314 "100nF" CC0603(1608) 44915.35,43535.43 r270 top
C315 "100nF" CC0603(1608) 44915.35,41328.74 r270 top
C316 "100nF" CC0603(1608) 44836.61,41328.74 r270 top
C317 "100nF" CC0603(1608) 44836.61,39732.28 r90 top
C318 "100nF" CC0603(1608) 44915.34,39732.28 r90 top
C319 "100nF" CC0603(1608) 45000,39730 r90 top
C320 "100nF" CC0603(1608) 44836.61,43039.37 r90 top
C321 "100nF" CC0603(1608) 44657.48,39911.42 r0 top
C322 "100nF" CC0603(1608) 44657.48,40068.9 r0 top
C323 "100nF" CC0603(1608) 44657.48,39990.16 r0 top
C324 "100nF" CC0603(1608) 46202.76,41330.71 r270 top
C325 "100nF" CC0603(1608) 46124.02,41330.71 r270 top
C326 "100nF" CC0603(1608) 46045.28,41330.71 r270 top
C327 "100nF" CC0603(1608) 44915.35,43039.37 r90 top
C328 "100nF" CC0603(1608) 46051.16,41937.01 r90 top
C329 "100nF" CC0603(1608) 46124.02,41937.01 r90 top
C330 "100nF" CC0603(1608) 46202.76,41937.01 r90 top
C331 "100nF" CC0603(1608) 46202.76,42433.07 r270 top
C332 "100nF" CC0603(1608) 46124.02,42433.07 r270 top
C333 "100nF" CC0603(1608) 46045.28,42433.07 r270 top
C334 "100nF" CC0603(1608) 46381.89,42096.46 r180 top
C335 "100nF" CC0603(1608) 46381.89,42175.2 r180 top
C336 "100nF" CC0603(1608) 46381.89,42253.94 r180 top
C337 "100nF" CC0603(1608) 46050,43040 r90 top
C338 "100nF" CC0603(1608) 46124.02,43039.37 r90 top
C339 "100nF" CC0603(1608) 46381.89,41072.83 r180 top
C340 "100nF" CC0603(1608) 46202.76,43039.37 r90 top
C341 "100nF" CC0603(1608) 46381.89,43198.82 r180 top
C342 "100nF" CC0603(1608) 46381.89,43277.56 r180 top
C343 "100nF" CC0603(1608) 46381.89,43356.3 r180 top
C344 "100nF" CC0603(1608) 46202.76,43535.43 r270 top
C345 "100nF" CC0603(1608) 46124.02,43535.43 r270 top
C346 "100nF" CC0603(1608) 46045.28,43535.43 r270 top
C347 "100nF" CC0603(1608) 45885.83,43336.61 r0 top
C348 "100nF" CC0603(1608) 45885.83,43257.87 r0 top
C349 "100nF" CC0603(1608) 45885.83,42155.51 r0 top
C350 "100nF" CC0603(1608) 45885.83,42234.25 r0 top
C351 "100nF" CC0603(1608) 45885.83,41131.89 r0 top
C352 "100nF" CC0603(1608) 45801.16,43151.57 r270 top
C353 "100nF" CC0603(1608) 45885.81,39816.93 r0 top
C354 "100nF" CC0603(1608) 45240.14,42320.87 r90 top
C355 "100nF" CC0603(1608) 45885.81,40919.29 r0 top
C356 "100nF" CC0603(1608) 45238.17,41218.5 r90 top
C357 "100nF" CC0603(1608) 45885.81,42021.65 r0 top
C358 "100nF" CC0603(1608) 45801.16,39844.49 r270 top
C359 "100nF" CC0603(1608) 45885.81,43124.02 r0 top
C360 "100nF" CC0603(1608) 46261.81,41937.01 r90 top
C361 "100nF" CC0603(1608) 46261.81,43039.37 r90 top
C362 "100nF" CC0603(1608) 45885.83,43415.35 r0 top
C363 "100nF" CC0603(1608) 44777.56,43039.37 r90 top
C364 "100nF" CC0603(1608) 46261.81,42433.07 r270 top
C365 "100nF" CC0603(1608) 46261.81,41330.71 r270 top
C366 "100nF" CC0603(1608) 46261.81,40228.35 r270 top
C367 "100nF" CC0603(1608) 44777.56,40228.35 r270 top
C368 "100nF" CC0603(1608) 44777.56,39732.28 r90 top
C369 "100nF" CC0603(1608) 45149.61,43159.45 r180 top
C370 "100nF" CC0603(1608) 44777.56,43535.43 r270 top
C371 "100nF" CC0603(1608) 45153.54,39852.36 r180 top
C372 "100nF" CC0603(1608) 44994.09,43039.37 r90 top
C373 "100nF" CC0603(1608) 45149.61,43316.93 r180 top
C374 "100nF" CC0603(1608) 44836.61,42433.07 r270 top
C375 "100nF" CC0603(1608) 44915.35,42433.07 r270 top
C376 "100nF" CC0603(1608) 44994.09,42433.07 r270 top
C377 "100nF" CC0603(1608) 44663.39,42273.62 r0 top
C378 "100nF" CC0603(1608) 44659.45,42194.88 r0 top
C379 "100nF" CC0603(1608) 44659.45,42116.14 r0 top
C380 "100nF" CC0603(1608) 44836.61,41937.01 r90 top
C381 "100nF" CC0603(1608) 44915.35,41937.01 r90 top
C382 "100nF" CC0603(1608) 44994.09,41937.01 r90 top
C383 "100nF" CC0603(1608) 45153.54,42135.83 r180 top
C384 "100nF" CC0603(1608) 45153.54,42214.57 r180 top
C385 "100nF" CC0603(1608) 44836.61,40834.65 r90 top
C386 "100nF" CC0603(1608) 44657.48,43297.24 r0 top
C387 "100nF" CC0603(1608) 44990,40230 r270 top
C388 "100nF" CC0603(1608) 44836.61,40228.35 r270 top
C389 "100nF" CC0603(1608) 44915.35,40228.35 r270 top
C390 "100nF" CC0603(1608) 44915.35,40834.65 r90 top
C391 "100nF" CC0603(1608) 44994.09,40834.65 r90 top
C392 "100nF" CC0603(1608) 45151.57,41033.46 r180 top
C393 "100nF" CC0603(1608) 45151.57,41112.2 r180 top
C394 "100nF" CC0603(1608) 44657.48,41013.78 r0 top
C395 "100nF" CC0603(1608) 44657.48,41092.52 r0 top
C396 "100nF" CC0603(1608) 44657.48,43218.5 r0 top
C397 "100nF" CC0603(1608) 44995,43535 r270 top
C398 "100nF" CC0603(1608) 44657.48,41171.26 r0 top
C399 "100nF" CC0603(1608) 45153.54,39931.1 r180 top
C400 "100nF" CC0603(1608) 45153.54,40009.84 r180 top
C401 "100nF" CC0603(1608) 46064.96,39732.28 r90 top
C402 "100nF" CC0603(1608) 46143.7,39732.28 r90 top
C403 "100nF" CC0603(1608) 46216.52,39732.28 r90 top
C404 "100nF" CC0603(1608) 46202.76,40228.35 r270 top
C405 "100nF" CC0603(1608) 46124.02,40228.35 r270 top
C406 "100nF" CC0603(1608) 46045.28,40228.35 r270 top
C407 "100nF" CC0603(1608) 46381.89,40049.21 r180 top
C408 "100nF" CC0603(1608) 46381.89,39970.47 r180 top
C409 "100nF" CC0603(1608) 46381.89,39891.73 r180 top
C410 "100nF" CC0603(1608) 45885.83,40029.53 r0 top
C411 "100nF" CC0603(1608) 45885.83,39950.79 r0 top
C412 "100nF" CC0603(1608) 46050,40835 r90 top
C413 "100nF" CC0603(1608) 46124.02,40834.65 r90 top
C414 "100nF" CC0603(1608) 46202.76,40834.65 r90 top
C415 "100nF" CC0603(1608) 46381.89,40994.09 r180 top
C416 "680uF/6.3V" D 47980,42739.02 r90 top
C417 "680uF/6.3V" D 47980,40530 r270 top
C418 "100nF" CC0603(1608) 48120,40545 r90 top
C419 "100nF" CC0603(1608) 48135,42730 r270 top
C420 "100nF" CC0603(1608) 47694.88,43423.23 r90 top
C421 "100nF" CC0603(1608) 47610.24,43450.79 r180 top
C422 "100nF" CC0603(1608) 48261.81,42049.21 r270 top
C423 "100nF" CC0603(1608) 47614.17,42348.43 r180 top
C424 "100nF" CC0603(1608) 48261.81,40946.85 r270 top
C425 "100nF" CC0603(1608) 47612.2,41246.06 r180 top
C426 "100nF" CC0603(1608) 47698.82,40116.14 r90 top
C427 "100nF" CC0603(1608) 47614.17,40143.7 r180 top
C428 "100nF" CC0603(1608) 48346.46,40108.27 r0 top
C429 "100nF" CC0603(1608) 47238.19,42433.07 r270 top
C430 "100nF" CC0603(1608) 48346.46,41210.63 r0 top
C431 "100nF" CC0603(1608) 47238.19,41328.74 r270 top
C432 "100nF" CC0603(1608) 48722.44,39732.28 r90 top
C433 "100nF" CC0603(1608) 48722.44,40834.65 r90 top
C434 "100nF" CC0603(1608) 48346.46,42312.99 r0 top
C435 "100nF" CC0603(1608) 47614.17,42057.09 r180 top
C436 "100nF" CC0603(1608) 47612.2,40954.72 r180 top
C437 "100nF" CC0603(1608) 47238.19,41937.01 r90 top
C438 "100nF" CC0603(1608) 48722.44,43535.43 r270 top
C439 "100nF" CC0603(1608) 47238.19,40834.65 r90 top
C440 "100nF" CC0603(1608) 48842.52,41151.57 r180 top
C441 "100nF" CC0603(1608) 47118.11,43375.98 r0 top
C442 "100nF" CC0603(1608) 48346.46,41053.15 r0 top
C443 "100nF" CC0603(1608) 47297.24,43535.43 r270 top
C444 "100nF" CC0603(1608) 47450,41328.35 r270 top
C445 "100nF" CC0603(1608) 47610.24,43238.19 r180 top
C446 "100nF" CC0603(1608) 47375.98,43535.43 r270 top
C447 "100nF" CC0603(1608) 47375.98,41328.74 r270 top
C448 "100nF" CC0603(1608) 47297.24,41328.74 r270 top
C449 "100nF" CC0603(1608) 47297.24,39732.28 r90 top
C450 "100nF" CC0603(1608) 47370,39730 r90 top
C451 "100nF" CC0603(1608) 47466.54,39732.28 r90 top
C452 "100nF" CC0603(1608) 47297.24,43039.37 r90 top
C453 "100nF" CC0603(1608) 47118.11,39911.42 r0 top
C454 "100nF" CC0603(1608) 47118.11,40068.9 r0 top
C455 "100nF" CC0603(1608) 47118.11,39990.16 r0 top
C456 "100nF" CC0603(1608) 48663.39,41330.71 r270 top
C457 "100nF" CC0603(1608) 48584.65,41330.71 r270 top
C458 "100nF" CC0603(1608) 48505.91,41330.71 r270 top
C459 "100nF" CC0603(1608) 47375.98,43039.37 r90 top
C460 "100nF" CC0603(1608) 48511.81,41937.01 r90 top
C461 "100nF" CC0603(1608) 48584.65,41937.01 r90 top
C462 "100nF" CC0603(1608) 48663.39,41937.01 r90 top
C463 "100nF" CC0603(1608) 48663.39,42433.07 r270 top
C464 "100nF" CC0603(1608) 48584.65,42433.07 r270 top
C465 "100nF" CC0603(1608) 48505.91,42433.07 r270 top
C466 "100nF" CC0603(1608) 48842.52,42096.46 r180 top
C467 "100nF" CC0603(1608) 48842.52,42175.2 r180 top
C468 "100nF" CC0603(1608) 48842.52,42253.94 r180 top
C469 "100nF" CC0603(1608) 48511.81,43039.37 r90 top
C470 "100nF" CC0603(1608) 48584.65,43039.37 r90 top
C471 "100nF" CC0603(1608) 48842.52,41072.83 r180 top
C472 "100nF" CC0603(1608) 48663.39,43039.37 r90 top
C473 "100nF" CC0603(1608) 48842.52,43198.82 r180 top
C474 "100nF" CC0603(1608) 48842.52,43277.56 r180 top
C475 "100nF" CC0603(1608) 48842.52,43356.3 r180 top
C476 "100nF" CC0603(1608) 48663.39,43535.43 r270 top
C477 "100nF" CC0603(1608) 48590.55,43535.43 r270 top
C478 "100nF" CC0603(1608) 48492.13,43535.43 r270 top
C479 "100nF" CC0603(1608) 48346.46,43336.61 r0 top
C480 "100nF" CC0603(1608) 48346.46,43257.87 r0 top
C481 "100nF" CC0603(1608) 48346.46,42155.51 r0 top
C482 "100nF" CC0603(1608) 48346.46,42234.25 r0 top
C483 "100nF" CC0603(1608) 48346.46,41131.89 r0 top
C484 "100nF" CC0603(1608) 48261.81,43151.57 r270 top
C485 "100nF" CC0603(1608) 48346.46,39816.93 r0 top
C486 "100nF" CC0603(1608) 47698.82,42320.87 r90 top
C487 "100nF" CC0603(1608) 48346.46,40919.29 r0 top
C488 "100nF" CC0603(1608) 47696.85,41218.5 r90 top
C489 "100nF" CC0603(1608) 48346.46,42021.65 r0 top
C490 "100nF" CC0603(1608) 48261.81,39844.49 r270 top
C491 "100nF" CC0603(1608) 48346.46,43124.02 r0 top
C492 "100nF" CC0603(1608) 48722.44,41937.01 r90 top
C493 "100nF" CC0603(1608) 48722.44,43039.37 r90 top
C494 "100nF" CC0603(1608) 48346.46,43415.35 r0 top
C495 "100nF" CC0603(1608) 47238.19,43039.37 r90 top
C496 "100nF" CC0603(1608) 48722.44,42433.07 r270 top
C497 "100nF" CC0603(1608) 48722.44,41330.71 r270 top
C498 "100nF" CC0603(1608) 48722.44,40228.35 r270 top
C499 "100nF" CC0603(1608) 47238.19,40228.35 r270 top
C500 "100nF" CC0603(1608) 47238.19,39732.28 r90 top
C501 "100nF" CC0603(1608) 47610.24,43159.45 r180 top
C502 "100nF" CC0603(1608) 47238.19,43535.43 r270 top
C503 "100nF" CC0603(1608) 47614.17,39852.36 r180 top
C504 "100nF" CC0603(1608) 47454.72,43039.37 r90 top
C505 "100nF" CC0603(1608) 47610.24,43316.93 r180 top
C506 "100nF" CC0603(1608) 47297.24,42433.07 r270 top
C507 "100nF" CC0603(1608) 47375.98,42433.07 r270 top
C508 "100nF" CC0603(1608) 47454.72,42433.07 r270 top
C509 "100nF" CC0603(1608) 47124.02,42273.62 r0 top
C510 "100nF" CC0603(1608) 47120.08,42194.88 r0 top
C511 "100nF" CC0603(1608) 47120.08,42116.14 r0 top
C512 "100nF" CC0603(1608) 47297.24,41937.01 r90 top
C513 "100nF" CC0603(1608) 47375.98,41937.01 r90 top
C514 "100nF" CC0603(1608) 47454.72,41937.01 r90 top
C515 "100nF" CC0603(1608) 47614.17,42135.83 r180 top
C516 "100nF" CC0603(1608) 47614.17,42214.57 r180 top
C517 "100nF" CC0603(1608) 47297.24,40834.65 r90 top
C518 "100nF" CC0603(1608) 47118.11,43297.24 r0 top
C519 "100nF" CC0603(1608) 47450,40228.35 r270 top
C520 "100nF" CC0603(1608) 47297.24,40228.35 r270 top
C521 "100nF" CC0603(1608) 47375.98,40228.35 r270 top
C522 "100nF" CC0603(1608) 47375.98,40834.65 r90 top
C523 "100nF" CC0603(1608) 47454.72,40834.65 r90 top
C524 "100nF" CC0603(1608) 47612.2,41033.46 r180 top
C525 "100nF" CC0603(1608) 47612.2,41112.2 r180 top
C526 "100nF" CC0603(1608) 47118.11,41013.78 r0 top
C527 "100nF" CC0603(1608) 47118.11,41092.52 r0 top
C528 "100nF" CC0603(1608) 47118.11,43218.5 r0 top
C529 "100nF" CC0603(1608) 47448.82,43535.43 r270 top
C530 "100nF" CC0603(1608) 47118.11,41171.26 r0 top
C531 "100nF" CC0603(1608) 47614.17,39931.1 r180 top
C532 "100nF" CC0603(1608) 47614.17,40009.84 r180 top
C533 "100nF" CC0603(1608) 48525.59,39732.28 r90 top
C534 "100nF" CC0603(1608) 48602.36,39732.28 r90 top
C535 "100nF" CC0603(1608) 48675.2,39732.28 r90 top
C536 "100nF" CC0603(1608) 48663.39,40228.35 r270 top
C537 "100nF" CC0603(1608) 48584.65,40228.35 r270 top
C538 "100nF" CC0603(1608) 48505.91,40228.35 r270 top
C539 "100nF" CC0603(1608) 48842.52,40049.21 r180 top
C540 "100nF" CC0603(1608) 48842.52,39970.47 r180 top
C541 "100nF" CC0603(1608) 48842.52,39891.73 r180 top
C542 "100nF" CC0603(1608) 48346.46,40029.53 r0 top
C543 "100nF" CC0603(1608) 48346.46,39950.79 r0 top
C544 "100nF" CC0603(1608) 48510,40835 r90 top
C545 "100nF" CC0603(1608) 48584.65,40834.65 r90 top
C546 "100nF" CC0603(1608) 48663.39,40834.65 r90 top
C547 "100nF" CC0603(1608) 48842.52,40994.09 r180 top
C548 "4.7uF" CAP1210(3225)_TAN 42230,45020 r90 top
C549 "22uF" CAP1210(3225)_TAN 39735,45025 r270 top
C550 "22uF" CAP1210(3225)_TAN 41710,45025 r270 top
C551 "10nF" CC0603(1608) 42230,45145 r180 top
C552 "100nF" CC0603(1608) 42535,45190 r180 top
C553 "22uF" CC1210(3225) 42322.83,44291.34 r180 top
C554 "4.7uF" CC0805(2012) 42165.35,44003.94 r270 top
C555 "47uF" CAPC3225L 43393.7,43767.72 r180 top
C556 "10uF" CAPC2012L 43392.63,43666 r0 top
C557 "1nF" CC0603(1608) 42862.2,43889.76 r180 top
C558 "100nF" CC0603(1608) 42675,44150 r90 bottom
C559 "2200pF" CC0603(1608) 42569.52,44268 r90 bottom
C560 "1uF" CC0603(1608) 42248.03,44152.56 r90 bottom
C561 "100nF" CC0603(1608) 43204.72,43710.63 r270 top
C562 "10uF" CC0805(2012) 43204.72,43602.36 r90 top
C563 "10uF" CC0805(2012) 43061.02,43500 r0 top
C564 "22nF" CC0603(1608) 45393.7,44070 r180 bottom
C565 "1500uF/4V" F12 46342.52,44240.16 r0 top locked
C566 "1500uF/4V" F12 45897.64,44240.16 r0 top locked
C567 "680uF/6.3V" D 46181.1,43767.72 r0 top
C568 "22uF" CC1210(3225) 44767.72,44405.51 r180 top
C569 "22uF" CC1210(3225) 44767.72,44291.34 r180 top
C570 "4.7uF" CC0805(2012) 44610.24,44003.94 r270 top
C571 "47uF" CAPC3225L 45854.33,43767.72 r180 top
C572 "10uF" CAPC2012L 45853.26,43666 r0 top
C573 "1nF" CC0603(1608) 45307.09,43889.76 r180 top
C574 "100nF" CC0603(1608) 45125,44150 r90 bottom
C575 "2200pF" CC0603(1608) 45014.4,44268 r90 bottom
C576 "1uF" CC0603(1608) 44692.91,44152.56 r90 bottom
C577 "100nF" CC0603(1608) 45665.35,43710.63 r270 top
C578 "10uF" CC0805(2012) 45665.35,43602.36 r90 top
C579 "10uF" CC0805(2012) 45521.65,43500 r0 top
C580 "22nF" CC0603(1608) 47748.03,44060 r180 bottom
C581 "1500uF/4V" F12 48696.85,44240.16 r0 top locked
C582 "1500uF/4V" F12 48251.97,44240.16 r0 top locked
C583 "680uF/6.3V" D 48641.73,43767.72 r0 top
C584 "22uF" CC1210(3225) 47122.05,44405.51 r180 top
C585 "22uF" CC1210(3225) 47122.05,44291.34 r180 top
C586 "4.7uF" CC0805(2012) 46964.57,44003.94 r270 top
C587 "47uF" CAPC3225L 48314.96,43767.72 r180 top
C588 "10uF" CAPC2012L 48313.89,43666 r0 top
C589 "1nF" CC0603(1608) 47661.42,43889.76 r180 top
C590 "100nF" CC0603(1608) 47470,44150 r90 bottom
C591 "2200pF" CC0603(1608) 47368.73,44268 r90 bottom
C592 "1uF" CC0603(1608) 47047.24,44147.56 r90 bottom
C593 "100nF" CC0603(1608) 48125.98,43710.63 r270 top
C594 "10uF" CC0805(2012) 48125.98,43602.36 r90 top
C595 "10uF" CC0805(2012) 47982.28,43500 r0 top
C596 "1500uF/4V" F12 43897.64,44240.16 r0 top locked
C597 "1500uF/4V" F12 43452.76,44240.16 r0 top locked
C598 "22nF" CC0603(1608) 42948.82,44055 r180 bottom
C599 "680uF/6.3V" D 43720.47,43767.72 r0 top
C600 "22uF" CC1210(3225) 42322.83,44405.51 r180 top
C601 "100nF" CC0603(1608) 44340,41410 r180 top
C602 "22uF" CAP1210(3225)_TAN 44292.09,42945 r180 top
C603 "6.8nF" CC0603(1608) 42681.97,45025 r0 top
C604 "22pF" CC0603(1608) 40230,45140 r180 top
C605 "100nF" CC0603(1608) 40135,45170 r270 top
C606 "470uF/16V" E12 46790,44540 r90 top
C607 "470uF/16V" E12 39636.81,44351.38 r90 top
C608 "470uF/16V" E12 42014.76,44563.98 r90 top
C609 "470uF/16V" E12 44412.4,44512.8 r90 top
D1 "Diode 1N4148" CD3216-1206 39765,44825 r90 top
FAN1 "Header 4" 4PINFAN 39520,44795 r90 top
FB1 "600/100M" FB0603(1608) 40198.82,43397.64 r0 top
FB2 "600/100M" FB0603(1608) 40202.76,42293.31 r0 top
FB3 "600/100M" FB0603(1608) 40200.79,41190.94 r0 top
FB4 "600/100M" FB0603(1608) 40202.76,40088.58 r0 top
FB5 "600/100M" FB0603(1608) 40994.09,39872.05 r180 top
FB6 "600/100M" FB0603(1608) 40992.13,40974.41 r180 top
FB7 "600/100M" FB0603(1608) 40994.09,42076.77 r180 top
FB8 "600/100M" FB0603(1608) 40992.13,43179.13 r180 top
FB9 "600/100M" FB0603(1608) 42659.45,43395.67 r0 top
FB10 "600/100M" FB0603(1608) 42663.39,42293.31 r0 top
FB11 "600/100M" FB0603(1608) 42661.42,41190.94 r0 top
FB12 "600/100M" FB0603(1608) 42663.39,40088.58 r0 top
FB13 "600/100M" FB0603(1608) 43454.72,39872.05 r180 top
FB14 "600/100M" FB0603(1608) 43454.72,40974.41 r180 top
FB15 "600/100M" FB0603(1608) 43454.72,42076.77 r180 top
FB16 "600/100M" FB0603(1608) 43454.72,43179.13 r180 top
FB17 "600/100M" FB0603(1608) 45120.06,43395.67 r0 top
FB18 "600/100M" FB0603(1608) 45124,42293.31 r0 top
FB19 "600/100M" FB0603(1608) 45122.03,41190.94 r0 top
FB20 "600/100M" FB0603(1608) 45124,40088.58 r0 top
FB21 "600/100M" FB0603(1608) 45915.34,39872.05 r180 top
FB22 "600/100M" FB0603(1608) 45915.34,40974.41 r180 top
FB23 "600/100M" FB0603(1608) 45915.34,42076.77 r180 top
FB24 "600/100M" FB0603(1608) 45915.34,43179.13 r180 top
FB25 "600/100M" FB0603(1608) 47580.71,43395.67 r0 top
FB26 "600/100M" FB0603(1608) 47584.65,42293.31 r0 top
FB27 "600/100M" FB0603(1608) 47582.68,41190.94 r0 top
FB28 "600/100M" FB0603(1608) 47584.65,40088.58 r0 top
FB29 "600/100M" FB0603(1608) 48375.98,39872.05 r180 top
FB30 "600/100M" FB0603(1608) 48375.98,40974.41 r180 top
FB31 "600/100M" FB0603(1608) 48375.98,42076.77 r180 top
FB32 "600/100M" FB0603(1608) 48375.98,43179.13 r180 top
FB33 "MB" INDC3216L 39910,44875 r0 top
FB34 "MB" INDC3216L 39910,44975 r0 top
FB35 "MB" INDC3216L 39910,45185 r0 top
FB36 "MB" INDC3216L 39910,45085 r0 top
J1 "CTRL" 8Pin_180 40795.63,45130 r0 top
L1 "0.44uH/30A" IHLP5050 40557.09,44194.88 r0 top locked
L2 "0.44uH/30A" IHLP5050 42899.61,44194.88 r0 top locked
L3 "0.44uH/30A" IHLP5050 45344.49,44194.88 r0 top locked
L4 "0.44uH/30A" IHLP5050 47698.82,44194.88 r0 top locked
L5 "10uH/4A" SMD_L_7.4x7.4 41965,45050 r180 top
M1 "Mount Hole" HOLE_3.2#1 39527.56,44724.41 r0 top locked
M2 "Mount Hole" HOLE_3.2#2 39527.56,44055.12 r0 top locked
M3 "Mount Hole" HOLE_3.2#2 49055.12,44055.12 r0 top
M4 "Mount Hole" MHOLE2 39527.56,43740.16 r0 top locked
M5 "Mount Hole" MHOLE2 39527.56,39527.56 r0 top locked
M6 "Mount Hole" MHOLE2 41673.23,39527.56 r0 top locked
M7 "Mount Hole" MHOLE2 41673.23,43740.16 r0 top locked
M8 "Mount Hole" MHOLE2 40600.39,41633.86 r0 top locked
M9 "Mount Hole" MHOLE2 41988.19,43740.16 r0 top locked
M10 "Mount Hole" MHOLE2 41988.19,39527.56 r0 top locked
M11 "Mount Hole" MHOLE2 44133.86,39527.56 r0 top locked
M12 "Mount Hole" MHOLE2 44133.86,43740.16 r0 top locked
M13 "Mount Hole" MHOLE2 43061.02,41633.86 r0 top locked
M14 "Mount Hole" MHOLE2 44448.82,43740.16 r0 top locked
M15 "Mount Hole" MHOLE2 44448.82,39527.56 r0 top locked
M16 "Mount Hole" MHOLE2 46594.49,39527.56 r0 top locked
M17 "Mount Hole" MHOLE2 46594.49,43740.16 r0 top locked
M18 "Mount Hole" MHOLE2 45521.67,41633.86 r0 top locked
M19 "Mount Hole" MHOLE2 46909.45,43740.16 r0 top locked
M20 "Mount Hole" MHOLE2 46909.45,39527.56 r0 top locked
M21 "Mount Hole" MHOLE2 49055.12,39527.56 r0 top locked
M22 "Mount Hole" MHOLE2 49055.12,43740.16 r0 top locked
M23 "Mount Hole" MHOLE2 47982.28,41633.86 r0 top locked
M27 "Mount Hole" HOLE_3.2#1 44291.34,44724.41 r0 top
M28 "Mount Hole" HOLE_3.2#2 44291.34,44055.12 r0 top
M32 "Mount Hole" HOLE_3.2#1 49055.12,44724.41 r0 top
MAKE1 "MASK" MASK 48935,44975 r0 top
MAKE2 "MASK" MASK 39620,39770 r90 top
MAKE3 "MASK" MASK 48975,39770 r270 bottom
MAKE4 "MASK" MASK 39720,45155 r270 bottom
MAKE5 "MASK" MASK 48990,39740 r90 top
MAKE6 "MASK" MASK 39735,45190 r90 top
MAKE7 "MASK" MASK 39606.3,45364.17 r90 top
MAKE8 "MASK" MASK 48976.38,45364.17 r90 top
MAKE9 "MASK" MASK 48976.38,45364.17 r270 bottom
MAKE10 "MASK" MASK 39606.3,45364.17 r270 bottom
P1 "+12V" TERMINAL_3 43396.85,45106.3 r180 top locked
P2 "GND" TERMINAL_3 43996.06,45106.3 r180 top locked
POWER "Header 4" 4Pin_180 41365,45130 r0 top
R1 "57.6K" RR0603(1608) 40496.06,44065 r90 bottom
R2 "200K" RR0603(1608) 39763,44084 r270 top
R3 "8.2K/1%" RR0603(1608) 40519.68,43842.52 r180 top
R4 "2" RR0603(1608) 40300,44070 r0 bottom
R5 "1K" RR0603(1608) 40064,43923 r0 top
R6 "100K" RR0603(1608) 39885.83,44031.5 r270 top
R7 "100K" RR0603(1608) 39735,43969 r180 top
R8 "200K" RR0603(1608) 39790,44060 r180 bottom
R9 "619K" RR0603(1608) 39790,43960 r180 bottom
R10 "182K" RR0603(1608) 39790,44010 r180 bottom
R11 "3" RR0603(1608) 40153,44295 r180 bottom
R12 "9.76K/1%" RR0603(1608) 40409.45,43842.52 r180 top
R13 "2.49K/1%" RR0603(1608) 40600.39,43562.99 r0 top
R14 "10K/1%" RR0603(1608) 40507.87,43533.46 r90 top
R15 "NC" RR0603(1608) 40520,43640 r90 top
R16 "1M" RR0603(1608) 40122.05,43515.75 r0 top
R17 "0" RR0603(1608) 40120.08,43627.95 r90 top
R18 "10K" RR0603(1608) 39791.34,43724.41 r180 top
R19 "270" RR0603(1608) 48235,43545 r270 top
R20 "270" RR0603(1608) 48185,43545 r270 top
R21 "10K" RR0603(1608) 48541.34,43535.43 r90 top
R22 "100K" RR0603(1608) 42640,45105 r90 top
R23 "10K" RR0603(1608) 40355,45080 r180 top
R24 "100" RR0603(1608) 40355,45140 r0 top
R25 "4.7K" RR0603(1608) 40230,45080 r0 top
R26 "4.7K" RR0603(1608) 40230,45200 r0 top
R27 "100" RR0603(1608) 40355,45200 r0 top
R28 "100K" RR0603(1608) 42077.52,43969 r180 top
R29 "200K" RR0603(1608) 42135,44065 r180 bottom
R30 "619K" RR0603(1608) 42135,43965 r180 bottom
R31 "182K" RR0603(1608) 42135,44015 r180 bottom
R32 "3" RR0603(1608) 42495.52,44295 r180 bottom
R33 "9.76K/1%" RR0603(1608) 42751.97,43842.52 r180 top
R34 "2.49K/1%" RR0603(1608) 43061.02,43562.99 r0 top
R35 "10K/1%" RR0603(1608) 42968.5,43533.46 r90 top
R36 "57.6K" RR0603(1608) 45283.46,44065 r90 bottom
R37 "200K" RR0603(1608) 44550.4,44084 r270 top
R38 "8.2K/1%" RR0603(1608) 45307.09,43842.52 r180 top
R39 "2" RR0603(1608) 45095,44070 r0 bottom
R40 "1K" RR0603(1608) 44851.4,43923 r0 top
R41 "100K" RR0603(1608) 44673.23,44031.5 r270 top
R42 "100K" RR0603(1608) 44522.4,43969 r180 top
R43 "200K" RR0603(1608) 44570,44055 r180 bottom
R44 "619K" RR0603(1608) 44570,43955 r180 bottom
R45 "182K" RR0603(1608) 44570,44005 r180 bottom
R46 "3" RR0603(1608) 44940.4,44295 r180 bottom
R47 "9.76K/1%" RR0603(1608) 45196.85,43842.52 r180 top
R48 "2.49K/1%" RR0603(1608) 45521.65,43562.99 r0 top
R49 "10K/1%" RR0603(1608) 45429.13,43533.46 r90 top
R50 "57.6K" RR0603(1608) 47637.8,44065 r90 bottom
R51 "200K" RR0603(1608) 46904.73,44084 r270 top
R52 "8.2K/1%" RR0603(1608) 47661.42,43842.52 r180 top
R53 "2" RR0603(1608) 47440,44070 r0 bottom
R54 "1K" RR0603(1608) 47205.73,43923 r0 top
R55 "100K" RR0603(1608) 47027.56,44031.5 r270 top
R56 "100K" RR0603(1608) 46876.73,43969 r180 top
R57 "200K" RR0603(1608) 46930,44055 r180 bottom
R58 "619K" RR0603(1608) 46930,43955 r180 bottom
R59 "182K" RR0603(1608) 46930,44005 r180 bottom
R60 "3" RR0603(1608) 47294.73,44295 r180 bottom
R61 "9.76K/1%" RR0603(1608) 47551.18,43842.52 r180 top
R62 "2.49K/1%" RR0603(1608) 47982.28,43562.99 r0 top
R63 "10K/1%" RR0603(1608) 47889.76,43533.46 r90 top
R64 "57.6K" RR0603(1608) 42838.58,44065 r90 bottom
R65 "200K" RR0603(1608) 42105.52,44084 r270 top
R66 "8.2K/1%" RR0603(1608) 42862.2,43842.52 r180 top
R67 "2" RR0603(1608) 42645,44070 r0 bottom
R68 "1K" RR0603(1608) 42406.52,43923 r0 top
R69 "100K" RR0603(1608) 42228.35,44031.5 r270 top
R70 "4.7K" RR0603(1608) 39690,44825 r90 top
R71 "26.1K/1%" RR0603(1608) 42505,44915 r0 top
R72 "10k/1%" RR0603(1608) 42620,44915 r180 top
R73 "6.8K" RR0603(1608) 42680,44970 r0 top
R74 "4.7K" RR0603(1608) 44365,41825 r90 top
RF "Green" LED0603(1608) 48185,43430 r270 top
TF "Green" LED0603(1608) 48235,43430 r270 top
TP1 "VOUT" TP_SMD_1.0 41433.07,43929.13 r0 top
TP2 "+12V" TP 40204.72,44736.22 r0 top
TP3 "GND" TP 40205,44505 r0 top
TP4 "TP" TP_SMD 47300.43,42736.22 r0 top
TP5 "TP" TP_SMD 39918.54,42736.22 r0 top
TP6 "TP" TP_SMD 39918.54,41633.86 r90 top
TP7 "TP" TP_SMD 39918.54,40531.5 r90 top
TP8 "TP" TP_SMD 40493.82,39726 r90 top
TP9 "TP" TP_SMD 40069.65,42736.22 r0 top
TP10 "TP" TP_SMD 40049.96,42795.28 r90 top
TP11 "TP" TP_SMD 40069.65,41633.86 r0 top
TP12 "TP" TP_SMD 40049.96,41692.91 r90 top
TP13 "TP" TP_SMD 40069.65,40531.5 r90 top
TP14 "TP" TP_SMD 40049.96,40590.55 r90 top
TP15 "TP" TP_SMD 40600,39810.18 r90 top
TP16 "TP" TP_SMD 40660,39783.18 r90 top
TP17 "TP" TP_SMD 39898.86,42795.28 r90 top
TP18 "TP" TP_SMD 40089.33,42854.33 r90 top
TP19 "TP" TP_SMD 39898.86,41692.91 r90 top
TP20 "TP" TP_SMD 40089.33,41751.97 r90 top
TP21 "TP" TP_SMD 39905,40590.55 r90 top
TP22 "TP" TP_SMD 40089.33,40649.61 r90 top
TP23 "TP" TP_SMD 40636.18,39702 r90 top
TP24 "TP" TP_SMD 40530,39833.43 r90 top
TP25 "TP" TP_SMD 40340,43625.98 r90 top
TP26 "TP" TP_SMD 40413.82,43625 r90 top
TP27 "TP" TP_SMD 40418.82,43700 r90 top
TP28 "TP" TP_SMD 39860,43724.41 r90 top
TP29 "TP" TP_SMD 41278.31,40531.5 r90 top
TP30 "TP" TP_SMD 41278.31,41633.86 r90 top
TP31 "TP" TP_SMD 41278.31,42736.22 r90 top
TP32 "TP" TP_SMD 41785,43436.63 r90 top
TP33 "TP" TP_SMD 41127.2,40531.5 r90 top
TP34 "TP" TP_SMD 41146.89,40472.44 r90 top
TP35 "TP" TP_SMD 41127.2,41633.86 r90 top
TP36 "TP" TP_SMD 41146.89,41574.8 r90 top
TP37 "TP" TP_SMD 41127.2,42736.22 r90 top
TP38 "TP" TP_SMD 41146.89,42677.17 r90 top
TP39 "TP" TP_SMD 41850.39,43547.99 r90 top
TP40 "TP" TP_SMD 41920,43456.13 r90 top
TP41 "TP" TP_SMD 41297.99,40472.44 r90 top
TP42 "TP" TP_SMD 41107.52,40413.39 r90 top
TP43 "TP" TP_SMD 41297.99,41574.8 r90 top
TP44 "TP" TP_SMD 41107.52,41515.75 r90 top
TP45 "TP" TP_SMD 41297.99,42677.17 r90 top
TP46 "TP" TP_SMD 41107.52,42618.11 r90 top
TP47 "TP" TP_SMD 41850,43417.13 r90 top
TP48 "TP" TP_SMD 41748.82,43536 r90 top
TP49 "TP" TP_SMD 42379.17,42736.22 r90 top
TP50 "TP" TP_SMD 42379.17,41633.86 r90 top
TP51 "TP" TP_SMD 42379.17,40531.5 r90 top
TP52 "TP" TP_SMD 42990.44,39690.62 r90 top
TP53 "TP" TP_SMD 42530.28,42736.22 r0 top
TP54 "TP" TP_SMD 42510.59,42795.28 r90 top
TP55 "TP" TP_SMD 42530.28,41633.86 r90 top
TP56 "TP" TP_SMD 42510.59,41692.91 r90 top
TP57 "TP" TP_SMD 42530.28,40531.5 r90 top
TP58 "TP" TP_SMD 42510.59,40590.55 r90 top
TP59 "TP" TP_SMD 43060.44,39810.98 r90 top
TP60 "TP" TP_SMD 43120.44,39783.98 r90 top
TP61 "TP" TP_SMD 42359.49,42795.28 r90 top
TP62 "TP" TP_SMD 42549.96,42854.33 r90 top
TP63 "TP" TP_SMD 42359.49,41692.91 r90 top
TP64 "TP" TP_SMD 42549.96,41751.97 r90 top
TP65 "TP" TP_SMD 42359.49,40590.55 r90 top
TP66 "TP" TP_SMD 42549.96,40649.61 r90 top
TP67 "TP" TP_SMD 43060.44,39666.62 r90 top
TP68 "TP" TP_SMD 42990,39829.23 r90 top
